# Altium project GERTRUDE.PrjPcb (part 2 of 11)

## Sheet MODULE.SchDoc: MODULE
size A3; Author: Silvio Navaretti; CompanyName: ARDUINO; DrawnBy: Silvio Navaretti; Engineer: Silvio Navaretti; Organization: ARDUINO; SheetNumber: 2; SheetTotal: 51; RevAuthor: Silvio Navaretti
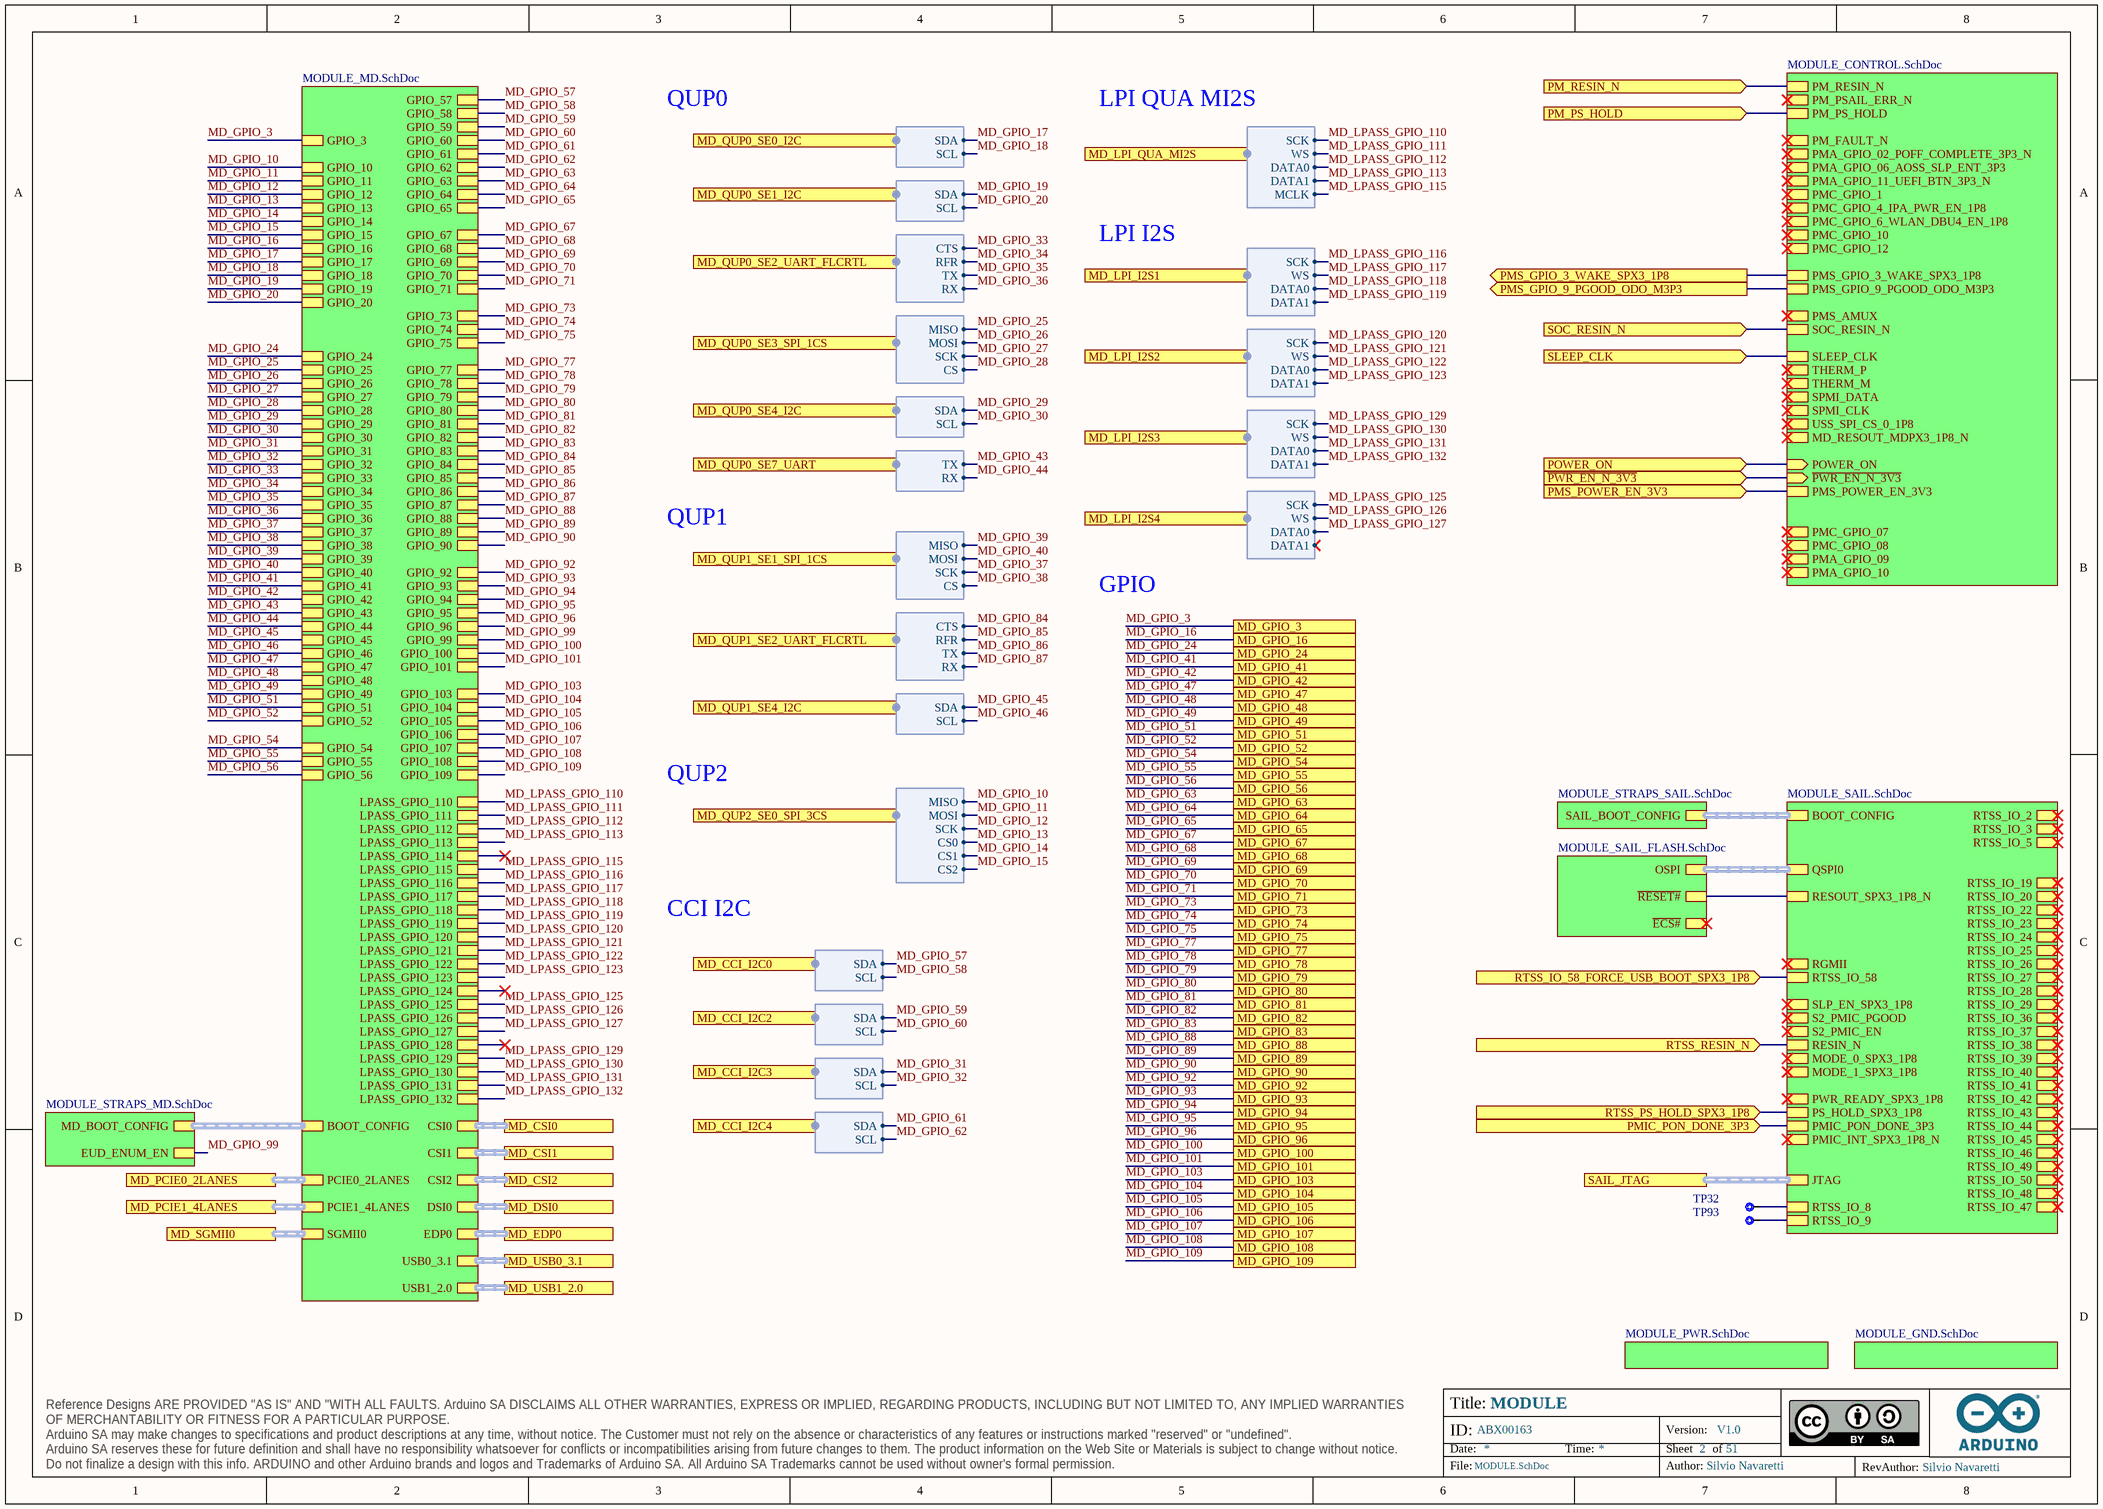
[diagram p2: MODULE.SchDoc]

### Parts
TP32  Test point 1.00mm  [TP-1.00MM]  (value not drawn)  (no BOM)
TP93  Test point 1.00mm  [TP-1.00MM]  (value not drawn)  (no BOM)

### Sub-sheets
MODULE_CONTROL = MODULE_CONTROL.SchDoc: PM_RESIN_N, PM_PSAIL_ERR_N, PM_PS_HOLD, PM_FAULT_N, PMA_GPIO_02_POFF_COMPLETE_3P3_N, PMA_GPIO_06_AOSS_SLP_ENT_3P3, PMA_GPIO_11_UEFI_BTN_3P3_N, PMC_GPIO_1, PMC_GPIO_4_IPA_PWR_EN_1P8, PMC_GPIO_6_WLAN_DBU4_EN_1P8, PMC_GPIO_10, PMC_GPIO_12, PMS_GPIO_3_WAKE_SPX3_1P8, PMS_GPIO_9_PGOOD_ODO_M3P3, PMS_AMUX, SOC_RESIN_N, SLEEP_CLK, THERM_P, THERM_M, SPMI_DATA, SPMI_CLK, USS_SPI_CS_0_1P8, MD_RESOUT_MDPX3_1P8_N, POWER_ON (in), ~{PWR_EN_N_3V3} (in), PMA_GPIO_09, PMA_GPIO_10, PMC_GPIO_07, PMC_GPIO_08, PMS_POWER_EN_3V3
MODULE_GND = MODULE_GND.SchDoc: no entries
MODULE_PWR = MODULE_PWR.SchDoc: no entries
MODULE_SAIL = MODULE_SAIL.SchDoc: JTAG (harness SOM_SAIL_JTAG), RGMII (harness SOM_SAIL_RGMII), SLP_EN_SPX3_1P8, S2_PMIC_PGOOD, S2_PMIC_EN, RESIN_N, MODE_0_SPX3_1P8, MODE_1_SPX3_1P8, PWR_READY_SPX3_1P8, PS_HOLD_SPX3_1P8, PMIC_PON_DONE_3P3, PMIC_INT_SPX3_1P8_N, BOOT_CONFIG (harness SOM_SAIL_BOOT_CONFIG), RTSS_IO_2, RTSS_IO_3, RTSS_IO_5, RTSS_IO_8, RTSS_IO_9, RTSS_IO_19, RTSS_IO_20, RTSS_IO_22, RTSS_IO_23, RTSS_IO_24, RTSS_IO_25, RTSS_IO_26, RTSS_IO_27, RTSS_IO_28, RTSS_IO_29, RTSS_IO_36, RTSS_IO_37, RTSS_IO_38, RTSS_IO_39, RTSS_IO_40, RTSS_IO_41, RTSS_IO_42, RTSS_IO_43, RTSS_IO_44, RTSS_IO_45, RTSS_IO_46, RTSS_IO_49, RTSS_IO_50, RTSS_IO_58, RTSS_IO_48, RTSS_IO_47, RESOUT_SPX3_1P8_N, QSPI0 (harness SOM_SAIL_QSPI0)
MODULE_SAIL_FLASH = MODULE_SAIL_FLASH.SchDoc: ~{RESET#}, ~{ECS#}, OSPI (harness SOM_SAIL_QSPI0)
MODULE_STRAPS_MD = MODULE_STRAPS_MD.SchDoc: MD_BOOT_CONFIG (harness SOM_MD_BOOT_CONFIG), EUD_ENUM_EN
MODULE_STRAPS_SAIL = MODULE_STRAPS_SAIL.SchDoc: SAIL_BOOT_CONFIG (harness SOM_SAIL_BOOT_CONFIG)
U_SOM_MD = MODULE_MD.SchDoc: GPIO_3, GPIO_10, GPIO_11, GPIO_12, GPIO_13, GPIO_14, GPIO_15, GPIO_16, GPIO_17, GPIO_18, GPIO_19, GPIO_20, GPIO_24, GPIO_25, GPIO_26, GPIO_27, GPIO_28, GPIO_29, GPIO_30, GPIO_31, GPIO_32, GPIO_33, GPIO_34, GPIO_35, GPIO_36, GPIO_37, GPIO_38, GPIO_39, GPIO_40, GPIO_42, GPIO_43, GPIO_45, GPIO_46, GPIO_47, GPIO_48, GPIO_52, GPIO_54, GPIO_55, GPIO_56, GPIO_57, GPIO_58, GPIO_59, GPIO_60, GPIO_61, GPIO_62, GPIO_63, GPIO_64, GPIO_65, GPIO_67, GPIO_68, GPIO_69, GPIO_70, GPIO_71, GPIO_73, GPIO_74, GPIO_75, GPIO_77, GPIO_78, GPIO_79, GPIO_80, GPIO_81, GPIO_83, GPIO_84, GPIO_85, GPIO_86, GPIO_87, GPIO_88, GPIO_89, GPIO_90, GPIO_92, GPIO_93, GPIO_94, GPIO_95, GPIO_99, GPIO_100, GPIO_101, GPIO_104, GPIO_105, GPIO_106, GPIO_107, GPIO_108, GPIO_109, LPASS_GPIO_110, LPASS_GPIO_111, LPASS_GPIO_112, LPASS_GPIO_113, LPASS_GPIO_114, LPASS_GPIO_115, LPASS_GPIO_116, LPASS_GPIO_117, LPASS_GPIO_118, LPASS_GPIO_119, LPASS_GPIO_120, LPASS_GPIO_121, LPASS_GPIO_122, LPASS_GPIO_123, LPASS_GPIO_124, LPASS_GPIO_125, LPASS_GPIO_126, LPASS_GPIO_127, LPASS_GPIO_128, LPASS_GPIO_129, LPASS_GPIO_130, LPASS_GPIO_131, LPASS_GPIO_132, SGMII0 (harness SOM_MD_SGMII0), EDP0 (harness SOM_MD_EDP0), USB0_3.1 (harness SOM_MD_USB0), USB1_2.0 (harness SOM_MD_USB1), PCIE1_4LANES (harness SOM_MD_PCIE1), BOOT_CONFIG (harness SOM_MD_BOOT_CONFIG), GPIO_44, CSI0 (harness MIPI_4LANES), CSI1 (harness MIPI_4LANES), CSI2 (harness MIPI_4LANES), DSI0 (harness MIPI_4LANES), GPIO_103, GPIO_82, GPIO_41, GPIO_96, GPIO_49, GPIO_51, PCIE0_2LANES (harness SOM_MD_PCIE0)

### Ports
MD_CCI_I2C0 (harness I2C), MD_CCI_I2C2 (harness I2C), MD_CCI_I2C3 (harness I2C), MD_CCI_I2C4 (harness I2C), MD_CSI0, MD_CSI1, MD_CSI2, MD_DSI0, MD_EDP0, MD_GPIO_3, MD_GPIO_16, MD_GPIO_24, MD_GPIO_41, MD_GPIO_42, MD_GPIO_47, MD_GPIO_48, MD_GPIO_49, MD_GPIO_51, MD_GPIO_52, MD_GPIO_54, MD_GPIO_55, MD_GPIO_56, MD_GPIO_63, MD_GPIO_64, MD_GPIO_65, MD_GPIO_67, MD_GPIO_68, MD_GPIO_69, MD_GPIO_70, MD_GPIO_71, MD_GPIO_73, MD_GPIO_74, MD_GPIO_75, MD_GPIO_77, MD_GPIO_78, MD_GPIO_79, MD_GPIO_80, MD_GPIO_81, MD_GPIO_82, MD_GPIO_83, MD_GPIO_88, MD_GPIO_89, MD_GPIO_90, MD_GPIO_92, MD_GPIO_93, MD_GPIO_94, MD_GPIO_95, MD_GPIO_96, MD_GPIO_100, MD_GPIO_101, MD_GPIO_103, MD_GPIO_104, MD_GPIO_105, MD_GPIO_106, MD_GPIO_107, MD_GPIO_108, MD_GPIO_109, MD_LPI_I2S1 (harness SOM_MD_I2S), MD_LPI_I2S2 (harness SOM_MD_I2S), MD_LPI_I2S3 (harness SOM_MD_I2S), MD_LPI_I2S4 (harness SOM_MD_I2S), MD_LPI_QUA_MI2S (harness SOM_MD_I2S_QUA), MD_PCIE0_2LANES, MD_PCIE1_4LANES, MD_QUP0_SE0_I2C (harness I2C), MD_QUP0_SE1_I2C (harness I2C), MD_QUP0_SE2_UART_FLCRTL (harness SOM_MD_UART_FLCRTL), MD_QUP0_SE3_SPI_1CS (harness SPI), MD_QUP0_SE4_I2C (harness I2C), MD_QUP0_SE7_UART (harness UART), MD_QUP1_SE1_SPI_1CS (harness SPI), MD_QUP1_SE2_UART_FLCRTL (harness SOM_MD_UART_FLCRTL), MD_QUP1_SE4_I2C (harness I2C), MD_QUP2_SE0_SPI_3CS (harness SOM_MD_SPI_3CS), MD_SGMII0, MD_USB0_3.1, MD_USB1_2.0, PM_PS_HOLD (in), PM_RESIN_N (in), PMIC_PON_DONE_3P3 (in), PMS_GPIO_3_WAKE_SPX3_1P8 (out), PMS_GPIO_9_PGOOD_ODO_M3P3 (out), PMS_POWER_EN_3V3 (in), POWER_ON (in), RTSS_IO_58_FORCE_USB_BOOT_SPX3_1P8 (in), RTSS_PS_HOLD_SPX3_1P8 (in), RTSS_RESIN_N (in), SAIL_JTAG, SLEEP_CLK (in), SOC_RESIN_N (in), ~{PWR_EN_N_3V3} (in)

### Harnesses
I2C: SDA, SCL
SOM_MD_I2S_QUA: SCK, WS, DATA0, DATA1, MCLK
SOM_MD_I2S: SCK, WS, DATA0, DATA1
SPI: SCK, MISO, MOSI, CS
SOM_MD_UART_FLCRTL: TX, CTS, RFR, RX
UART: TX, RX
SOM_MD_SPI_3CS: SCK, MISO, MOSI, CS0, CS1, CS2

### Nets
MD_GPIO_3: port MD_GPIO_3, sheet U_SOM_MD/GPIO_3
MD_GPIO_10: sheet U_SOM_MD/GPIO_10, port MD_QUP2_SE0_SPI_3CS.MISO
MD_GPIO_11: sheet U_SOM_MD/GPIO_11, port MD_QUP2_SE0_SPI_3CS.MOSI
MD_GPIO_12: sheet U_SOM_MD/GPIO_12, port MD_QUP2_SE0_SPI_3CS.SCK
MD_GPIO_13: sheet U_SOM_MD/GPIO_13, port MD_QUP2_SE0_SPI_3CS.CS0
MD_GPIO_14: sheet U_SOM_MD/GPIO_14, port MD_QUP2_SE0_SPI_3CS.CS1
MD_GPIO_15: sheet U_SOM_MD/GPIO_15, port MD_QUP2_SE0_SPI_3CS.CS2
MD_GPIO_16: port MD_GPIO_16, sheet U_SOM_MD/GPIO_16
MD_GPIO_17: sheet U_SOM_MD/GPIO_17, port MD_QUP0_SE0_I2C.SDA
MD_GPIO_18: sheet U_SOM_MD/GPIO_18, port MD_QUP0_SE0_I2C.SCL
MD_GPIO_19: sheet U_SOM_MD/GPIO_19, port MD_QUP0_SE1_I2C.SDA
MD_GPIO_20: sheet U_SOM_MD/GPIO_20, port MD_QUP0_SE1_I2C.SCL
MD_GPIO_24: port MD_GPIO_24, sheet U_SOM_MD/GPIO_24
MD_GPIO_25: sheet U_SOM_MD/GPIO_25, port MD_QUP0_SE3_SPI_1CS.MISO
MD_GPIO_26: sheet U_SOM_MD/GPIO_26, port MD_QUP0_SE3_SPI_1CS.MOSI
MD_GPIO_27: sheet U_SOM_MD/GPIO_27, port MD_QUP0_SE3_SPI_1CS.SCK
MD_GPIO_28: sheet U_SOM_MD/GPIO_28, port MD_QUP0_SE3_SPI_1CS.CS
MD_GPIO_29: sheet U_SOM_MD/GPIO_29, port MD_QUP0_SE4_I2C.SDA
MD_GPIO_30: sheet U_SOM_MD/GPIO_30, port MD_QUP0_SE4_I2C.SCL
MD_GPIO_31: sheet U_SOM_MD/GPIO_31, port MD_CCI_I2C3.SDA  [project net MD_CCI_I2C3.SDA]
MD_GPIO_32: sheet U_SOM_MD/GPIO_32, port MD_CCI_I2C3.SCL  [project net MD_CCI_I2C3.SCL]
MD_GPIO_33: sheet U_SOM_MD/GPIO_33, port MD_QUP0_SE2_UART_FLCRTL.CTS
MD_GPIO_34: sheet U_SOM_MD/GPIO_34, port MD_QUP0_SE2_UART_FLCRTL.RFR
MD_GPIO_35: sheet U_SOM_MD/GPIO_35, port MD_QUP0_SE2_UART_FLCRTL.TX
MD_GPIO_36: sheet U_SOM_MD/GPIO_36, port MD_QUP0_SE2_UART_FLCRTL.RX
MD_GPIO_37: sheet U_SOM_MD/GPIO_37, port MD_QUP1_SE1_SPI_1CS.SCK
MD_GPIO_38: sheet U_SOM_MD/GPIO_38, port MD_QUP1_SE1_SPI_1CS.CS
MD_GPIO_39: sheet U_SOM_MD/GPIO_39, port MD_QUP1_SE1_SPI_1CS.MISO
MD_GPIO_40: sheet U_SOM_MD/GPIO_40, port MD_QUP1_SE1_SPI_1CS.MOSI
MD_GPIO_41: port MD_GPIO_41, sheet U_SOM_MD/GPIO_41
MD_GPIO_42: port MD_GPIO_42, sheet U_SOM_MD/GPIO_42
MD_GPIO_43: sheet U_SOM_MD/GPIO_43, port MD_QUP0_SE7_UART.TX
MD_GPIO_44: sheet U_SOM_MD/GPIO_44, port MD_QUP0_SE7_UART.RX
MD_GPIO_45: sheet U_SOM_MD/GPIO_45, port MD_QUP1_SE4_I2C.SDA
MD_GPIO_46: sheet U_SOM_MD/GPIO_46, port MD_QUP1_SE4_I2C.SCL
MD_GPIO_47: port MD_GPIO_47, sheet U_SOM_MD/GPIO_47
MD_GPIO_48: port MD_GPIO_48, sheet U_SOM_MD/GPIO_48
MD_GPIO_49: port MD_GPIO_49, sheet U_SOM_MD/GPIO_49
MD_GPIO_51: port MD_GPIO_51, sheet U_SOM_MD/GPIO_51
MD_GPIO_52: port MD_GPIO_52, sheet U_SOM_MD/GPIO_52
MD_GPIO_54: port MD_GPIO_54, sheet U_SOM_MD/GPIO_54
MD_GPIO_55: port MD_GPIO_55, sheet U_SOM_MD/GPIO_55
MD_GPIO_56: port MD_GPIO_56, sheet U_SOM_MD/GPIO_56
MD_GPIO_57: sheet U_SOM_MD/GPIO_57, port MD_CCI_I2C0.SDA  [project net MD_CCI_I2C0.SDA]
MD_GPIO_58: sheet U_SOM_MD/GPIO_58, port MD_CCI_I2C0.SCL  [project net MD_CCI_I2C0.SCL]
MD_GPIO_59: sheet U_SOM_MD/GPIO_59, port MD_CCI_I2C2.SDA  [project net MD_CCI_I2C2.SDA]
MD_GPIO_60: sheet U_SOM_MD/GPIO_60, port MD_CCI_I2C2.SCL  [project net MD_CCI_I2C2.SCL]
MD_GPIO_61: sheet U_SOM_MD/GPIO_61, port MD_CCI_I2C4.SDA  [project net MD_CCI_I2C4.SDA]
MD_GPIO_62: sheet U_SOM_MD/GPIO_62, port MD_CCI_I2C4.SCL  [project net MD_CCI_I2C4.SCL]
MD_GPIO_63: port MD_GPIO_63, sheet U_SOM_MD/GPIO_63
MD_GPIO_64: port MD_GPIO_64, sheet U_SOM_MD/GPIO_64
MD_GPIO_65: port MD_GPIO_65, sheet U_SOM_MD/GPIO_65
MD_GPIO_67: port MD_GPIO_67, sheet U_SOM_MD/GPIO_67
MD_GPIO_68: port MD_GPIO_68, sheet U_SOM_MD/GPIO_68
MD_GPIO_69: port MD_GPIO_69, sheet U_SOM_MD/GPIO_69
MD_GPIO_70: port MD_GPIO_70, sheet U_SOM_MD/GPIO_70
MD_GPIO_71: port MD_GPIO_71, sheet U_SOM_MD/GPIO_71
MD_GPIO_73: port MD_GPIO_73, sheet U_SOM_MD/GPIO_73
MD_GPIO_74: port MD_GPIO_74, sheet U_SOM_MD/GPIO_74
MD_GPIO_75: port MD_GPIO_75, sheet U_SOM_MD/GPIO_75
MD_GPIO_77: port MD_GPIO_77, sheet U_SOM_MD/GPIO_77
MD_GPIO_78: port MD_GPIO_78, sheet U_SOM_MD/GPIO_78
MD_GPIO_79: port MD_GPIO_79, sheet U_SOM_MD/GPIO_79
MD_GPIO_80: port MD_GPIO_80, sheet U_SOM_MD/GPIO_80
MD_GPIO_81: port MD_GPIO_81, sheet U_SOM_MD/GPIO_81
MD_GPIO_82: port MD_GPIO_82, sheet U_SOM_MD/GPIO_82
MD_GPIO_83: port MD_GPIO_83, sheet U_SOM_MD/GPIO_83
MD_GPIO_84: sheet U_SOM_MD/GPIO_84, port MD_QUP1_SE2_UART_FLCRTL.CTS  [project net CTS_1V8]
MD_GPIO_85: sheet U_SOM_MD/GPIO_85, port MD_QUP1_SE2_UART_FLCRTL.RFR
MD_GPIO_86: sheet U_SOM_MD/GPIO_86, port MD_QUP1_SE2_UART_FLCRTL.TX
MD_GPIO_87: sheet U_SOM_MD/GPIO_87, port MD_QUP1_SE2_UART_FLCRTL.RX
MD_GPIO_88: port MD_GPIO_88, sheet U_SOM_MD/GPIO_88
MD_GPIO_89: port MD_GPIO_89, sheet U_SOM_MD/GPIO_89
MD_GPIO_90: port MD_GPIO_90, sheet U_SOM_MD/GPIO_90
MD_GPIO_92: port MD_GPIO_92, sheet U_SOM_MD/GPIO_92
MD_GPIO_93: port MD_GPIO_93, sheet U_SOM_MD/GPIO_93
MD_GPIO_94: port MD_GPIO_94, sheet U_SOM_MD/GPIO_94
MD_GPIO_95: port MD_GPIO_95, sheet U_SOM_MD/GPIO_95
MD_GPIO_96: port MD_GPIO_96, sheet U_SOM_MD/GPIO_96
MD_GPIO_99: sheet U_SOM_MD/GPIO_99, sheet MODULE_STRAPS_MD/EUD_ENUM_EN
MD_GPIO_100: port MD_GPIO_100, sheet U_SOM_MD/GPIO_100
MD_GPIO_101: port MD_GPIO_101, sheet U_SOM_MD/GPIO_101
MD_GPIO_103: port MD_GPIO_103, sheet U_SOM_MD/GPIO_103
MD_GPIO_104: port MD_GPIO_104, sheet U_SOM_MD/GPIO_104
MD_GPIO_105: port MD_GPIO_105, sheet U_SOM_MD/GPIO_105
MD_GPIO_106: port MD_GPIO_106, sheet U_SOM_MD/GPIO_106
MD_GPIO_107: port MD_GPIO_107, sheet U_SOM_MD/GPIO_107
MD_GPIO_108: port MD_GPIO_108, sheet U_SOM_MD/GPIO_108
MD_GPIO_109: port MD_GPIO_109, sheet U_SOM_MD/GPIO_109
MD_LPASS_GPIO_110: sheet U_SOM_MD/LPASS_GPIO_110, port MD_LPI_QUA_MI2S.SCK
MD_LPASS_GPIO_111: sheet U_SOM_MD/LPASS_GPIO_111, port MD_LPI_QUA_MI2S.WS
MD_LPASS_GPIO_112: sheet U_SOM_MD/LPASS_GPIO_112, port MD_LPI_QUA_MI2S.DATA0
MD_LPASS_GPIO_113: sheet U_SOM_MD/LPASS_GPIO_113, port MD_LPI_QUA_MI2S.DATA1
MD_LPASS_GPIO_115: sheet U_SOM_MD/LPASS_GPIO_115, port MD_LPI_QUA_MI2S.MCLK
MD_LPASS_GPIO_116: sheet U_SOM_MD/LPASS_GPIO_116, port MD_LPI_I2S1.SCK  [project net I2S_SCK]
MD_LPASS_GPIO_117: sheet U_SOM_MD/LPASS_GPIO_117, port MD_LPI_I2S1.WS  [project net I2S_WS]
MD_LPASS_GPIO_118: sheet U_SOM_MD/LPASS_GPIO_118, port MD_LPI_I2S1.DATA0  [project net I2S_DATA0]
MD_LPASS_GPIO_119: sheet U_SOM_MD/LPASS_GPIO_119, port MD_LPI_I2S1.DATA1  [project net I2S_DATA1]
MD_LPASS_GPIO_120: sheet U_SOM_MD/LPASS_GPIO_120, port MD_LPI_I2S2.SCK
MD_LPASS_GPIO_121: sheet U_SOM_MD/LPASS_GPIO_121, port MD_LPI_I2S2.WS
MD_LPASS_GPIO_122: sheet U_SOM_MD/LPASS_GPIO_122, port MD_LPI_I2S2.DATA0
MD_LPASS_GPIO_123: sheet U_SOM_MD/LPASS_GPIO_123, port MD_LPI_I2S2.DATA1
MD_LPASS_GPIO_125: sheet U_SOM_MD/LPASS_GPIO_125, port MD_LPI_I2S4.SCK
MD_LPASS_GPIO_126: sheet U_SOM_MD/LPASS_GPIO_126, port MD_LPI_I2S4.WS
MD_LPASS_GPIO_127: sheet U_SOM_MD/LPASS_GPIO_127, port MD_LPI_I2S4.DATA0
MD_LPASS_GPIO_129: sheet U_SOM_MD/LPASS_GPIO_129, port MD_LPI_I2S3.SCK
MD_LPASS_GPIO_130: sheet U_SOM_MD/LPASS_GPIO_130, port MD_LPI_I2S3.WS
MD_LPASS_GPIO_131: sheet U_SOM_MD/LPASS_GPIO_131, port MD_LPI_I2S3.DATA0
MD_LPASS_GPIO_132: sheet U_SOM_MD/LPASS_GPIO_132, port MD_LPI_I2S3.DATA1
PM_PS_HOLD: port PM_PS_HOLD, sheet MODULE_CONTROL/PM_PS_HOLD
RTSS_IO_58_FORCE_USB_BOOT_SPX3_1P8: port RTSS_IO_58_FORCE_USB_BOOT_SPX3_1P8, sheet MODULE_SAIL/RTSS_IO_58
RTSS_RESIN_N: port RTSS_RESIN_N, sheet MODULE_SAIL/RESIN_N
SLEEP_CLK: port SLEEP_CLK, sheet MODULE_CONTROL/SLEEP_CLK
NetMODULE1_A6: port PM_RESIN_N, sheet MODULE_CONTROL/PM_RESIN_N
NetMODULE1_AY42: port PMS_GPIO_9_PGOOD_ODO_M3P3, sheet MODULE_CONTROL/PMS_GPIO_9_PGOOD_ODO_M3P3
NetMODULE1_AY45: port PMIC_PON_DONE_3P3, sheet MODULE_SAIL/PMIC_PON_DONE_3P3
NetMODULE1_BA43: port PMS_POWER_EN_3V3, sheet MODULE_CONTROL/PMS_POWER_EN_3V3
NetMODULE1_BB43: port RTSS_PS_HOLD_SPX3_1P8, sheet MODULE_SAIL/PS_HOLD_SPX3_1P8
NetMODULE1_BB44: port PMS_GPIO_3_WAKE_SPX3_1P8, sheet MODULE_CONTROL/PMS_GPIO_3_WAKE_SPX3_1P8
NetMODULE1_BD41: sheet MODULE_SAIL/RESOUT_SPX3_1P8_N, sheet MODULE_SAIL_FLASH/~{RESET#}
NetMODULE1_BE36: TP93.X ; sheet MODULE_SAIL/RTSS_IO_9
NetMODULE1_BF36: TP32.X ; sheet MODULE_SAIL/RTSS_IO_8
NetMODULE1_D28: port SOC_RESIN_N, sheet MODULE_CONTROL/SOC_RESIN_N
NetR349_2: port POWER_ON, sheet MODULE_CONTROL/POWER_ON
NetR350_2: port ~{PWR_EN_N_3V3}, sheet MODULE_CONTROL/~{PWR_EN_N_3V3}

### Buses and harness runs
harness port MD_CSI0 = sheet U_SOM_MD/CSI0
harness port MD_CSI1 = sheet U_SOM_MD/CSI1
harness port MD_CSI2 = sheet U_SOM_MD/CSI2
harness port MD_DSI0 = sheet U_SOM_MD/DSI0
harness port MD_EDP0 = sheet U_SOM_MD/EDP0
harness port MD_PCIE0_2LANES = sheet U_SOM_MD/PCIE0_2LANES
harness port MD_PCIE1_4LANES = sheet U_SOM_MD/PCIE1_4LANES
harness port MD_SGMII0 = sheet U_SOM_MD/SGMII0
harness port MD_USB0_3.1 = sheet U_SOM_MD/USB0_3.1
harness port MD_USB1_2.0 = sheet U_SOM_MD/USB1_2.0
harness port SAIL_JTAG = sheet MODULE_SAIL/JTAG
harness sheet MODULE_SAIL/BOOT_CONFIG = sheet MODULE_STRAPS_SAIL/SAIL_BOOT_CONFIG
harness sheet MODULE_SAIL/QSPI0 = sheet MODULE_SAIL_FLASH/OSPI
harness sheet MODULE_STRAPS_MD/MD_BOOT_CONFIG = sheet U_SOM_MD/BOOT_CONFIG

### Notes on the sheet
- QUP0
- LPI QUA MI2S
- LPI I2S
- QUP1
- GPIO
- QUP2
- CCI I2C

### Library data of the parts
TP32 TP93 = UT0013-A.6: Part Number: This is not a component

## Sheet MODULE_GND.SchDoc: MODULE GND
size A3; Author: Silvio Navaretti; CompanyName: ARDUINO; DrawnBy: Silvio Navaretti; Engineer: Silvio Navaretti; Organization: ARDUINO; SheetNumber: 10; SheetTotal: 51; RevAuthor: Silvio Navaretti
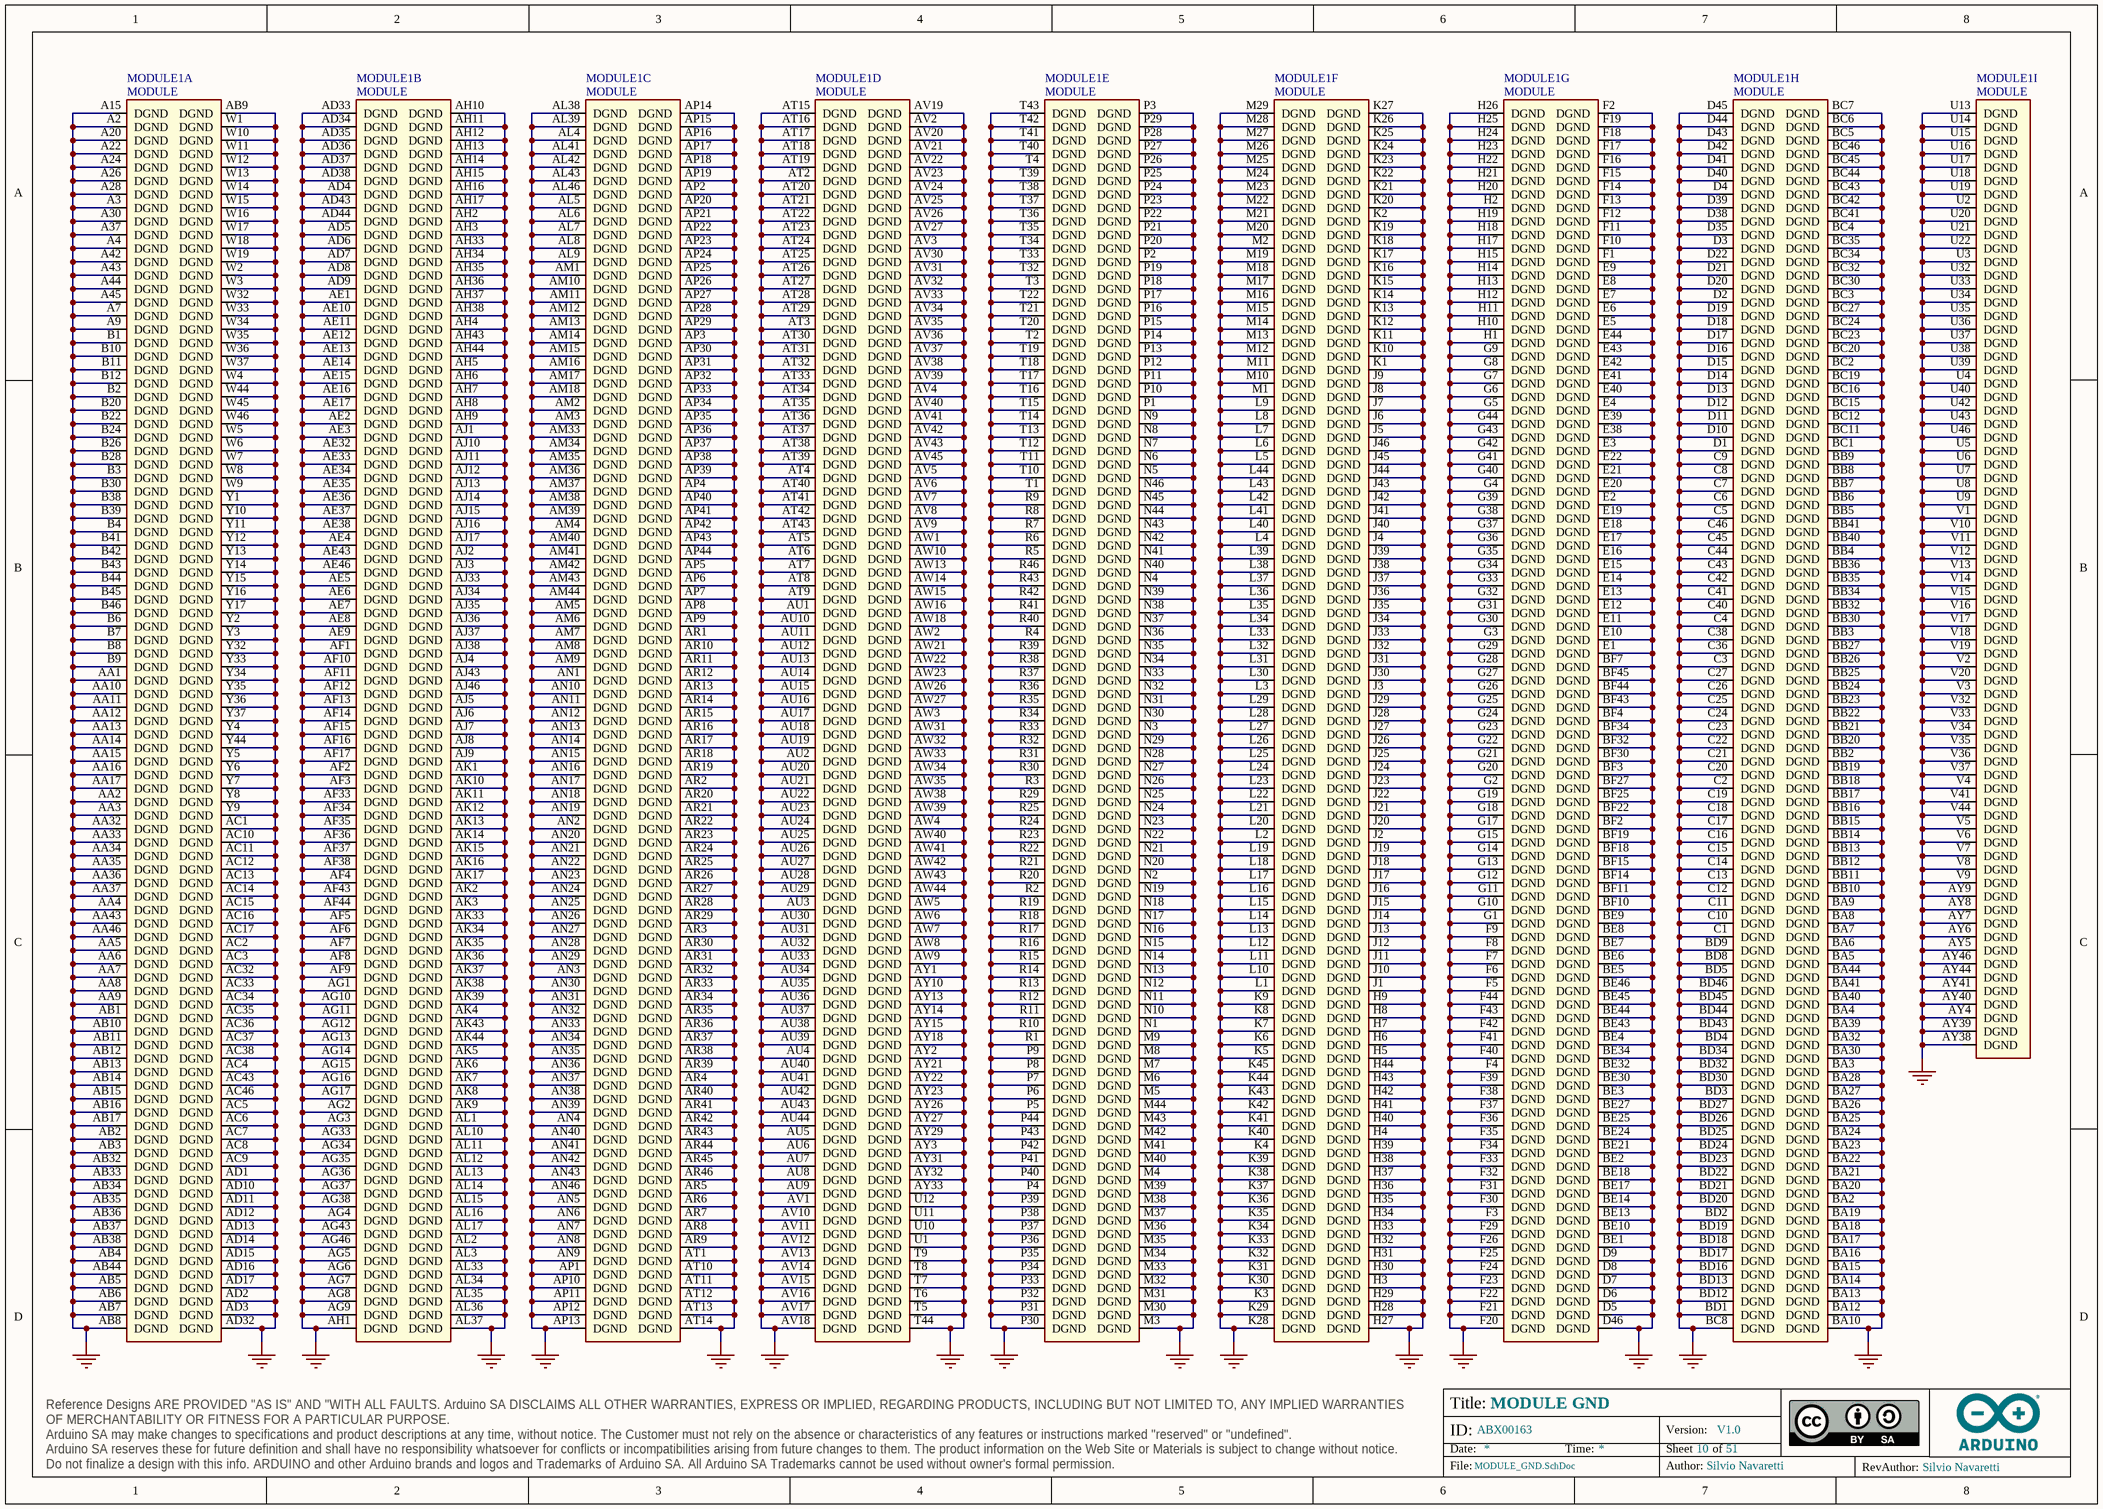
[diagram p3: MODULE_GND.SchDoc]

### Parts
MODULE1  MODULE  [MODULE]  (parts A,B,C,D,E,F,G,H,I of 22)

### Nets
GND: MODULE1.A2(DGND) MODULE1.A3(DGND) MODULE1.A4(DGND) MODULE1.A7(DGND) MODULE1.A9(DGND) MODULE1.A15(DGND) MODULE1.A20(DGND) MODULE1.A22(DGND) MODULE1.A24(DGND) MODULE1.A26(DGND) MODULE1.A28(DGND) MODULE1.A30(DGND) MODULE1.A37(DGND) MODULE1.A42(DGND) MODULE1.A43(DGND) MODULE1.A44(DGND) MODULE1.A45(DGND) MODULE1.AA1(DGND) MODULE1.AA2(DGND) MODULE1.AA3(DGND) MODULE1.AA4(DGND) MODULE1.AA5(DGND) MODULE1.AA6(DGND) MODULE1.AA7(DGND) MODULE1.AA8(DGND) MODULE1.AA9(DGND) MODULE1.AA10(DGND) MODULE1.AA11(DGND) MODULE1.AA12(DGND) MODULE1.AA13(DGND) MODULE1.AA14(DGND) MODULE1.AA15(DGND) MODULE1.AA16(DGND) MODULE1.AA17(DGND) MODULE1.AA32(DGND) MODULE1.AA33(DGND) MODULE1.AA34(DGND) MODULE1.AA35(DGND) MODULE1.AA36(DGND) MODULE1.AA37(DGND) MODULE1.AA43(DGND) MODULE1.AA46(DGND) MODULE1.AB1(DGND) MODULE1.AB2(DGND) MODULE1.AB3(DGND) MODULE1.AB4(DGND) MODULE1.AB5(DGND) MODULE1.AB6(DGND) MODULE1.AB7(DGND) MODULE1.AB8(DGND) MODULE1.AB9(DGND) MODULE1.AB10(DGND) MODULE1.AB11(DGND) MODULE1.AB12(DGND) MODULE1.AB13(DGND) MODULE1.AB14(DGND) MODULE1.AB15(DGND) MODULE1.AB16(DGND) MODULE1.AB17(DGND) MODULE1.AB32(DGND) MODULE1.AB33(DGND) MODULE1.AB34(DGND) MODULE1.AB35(DGND) MODULE1.AB36(DGND) MODULE1.AB37(DGND) MODULE1.AB38(DGND) MODULE1.AB44(DGND) MODULE1.AC1(DGND) MODULE1.AC2(DGND) MODULE1.AC3(DGND) MODULE1.AC4(DGND) MODULE1.AC5(DGND) MODULE1.AC6(DGND) MODULE1.AC7(DGND) MODULE1.AC8(DGND) MODULE1.AC9(DGND) MODULE1.AC10(DGND) MODULE1.AC11(DGND) MODULE1.AC12(DGND) MODULE1.AC13(DGND) MODULE1.AC14(DGND) MODULE1.AC15(DGND) MODULE1.AC16(DGND) MODULE1.AC17(DGND) MODULE1.AC32(DGND) MODULE1.AC33(DGND) MODULE1.AC34(DGND) MODULE1.AC35(DGND) MODULE1.AC36(DGND) MODULE1.AC37(DGND) MODULE1.AC38(DGND) MODULE1.AC43(DGND) MODULE1.AC46(DGND) MODULE1.AD1(DGND) MODULE1.AD2(DGND) MODULE1.AD3(DGND) MODULE1.AD4(DGND) MODULE1.AD5(DGND) MODULE1.AD6(DGND) MODULE1.AD7(DGND) MODULE1.AD8(DGND) MODULE1.AD9(DGND) MODULE1.AD10(DGND) MODULE1.AD11(DGND) MODULE1.AD12(DGND) MODULE1.AD13(DGND) MODULE1.AD14(DGND) MODULE1.AD15(DGND) MODULE1.AD16(DGND) MODULE1.AD17(DGND) MODULE1.AD32(DGND) MODULE1.AD33(DGND) MODULE1.AD34(DGND) MODULE1.AD35(DGND) MODULE1.AD36(DGND) MODULE1.AD37(DGND) MODULE1.AD38(DGND) MODULE1.AD43(DGND) MODULE1.AD44(DGND) MODULE1.AE1(DGND) MODULE1.AE2(DGND) MODULE1.AE3(DGND) MODULE1.AE4(DGND) MODULE1.AE5(DGND) MODULE1.AE6(DGND) MODULE1.AE7(DGND) MODULE1.AE8(DGND) MODULE1.AE9(DGND) MODULE1.AE10(DGND) MODULE1.AE11(DGND) MODULE1.AE12(DGND) MODULE1.AE13(DGND) MODULE1.AE14(DGND) MODULE1.AE15(DGND) MODULE1.AE16(DGND) MODULE1.AE17(DGND) MODULE1.AE32(DGND) MODULE1.AE33(DGND) MODULE1.AE34(DGND) MODULE1.AE35(DGND) MODULE1.AE36(DGND) MODULE1.AE37(DGND) MODULE1.AE38(DGND) MODULE1.AE43(DGND) MODULE1.AE46(DGND) MODULE1.AF1(DGND) MODULE1.AF2(DGND) MODULE1.AF3(DGND) MODULE1.AF4(DGND) MODULE1.AF5(DGND) MODULE1.AF6(DGND) MODULE1.AF7(DGND) MODULE1.AF8(DGND) MODULE1.AF9(DGND) MODULE1.AF10(DGND) MODULE1.AF11(DGND) MODULE1.AF12(DGND) MODULE1.AF13(DGND) MODULE1.AF14(DGND) MODULE1.AF15(DGND) MODULE1.AF16(DGND) MODULE1.AF17(DGND) MODULE1.AF33(DGND) MODULE1.AF34(DGND) MODULE1.AF35(DGND) MODULE1.AF36(DGND) MODULE1.AF37(DGND) MODULE1.AF38(DGND) MODULE1.AF43(DGND) MODULE1.AF44(DGND) MODULE1.AG1(DGND) MODULE1.AG2(DGND) MODULE1.AG3(DGND) MODULE1.AG4(DGND) MODULE1.AG5(DGND) MODULE1.AG6(DGND) MODULE1.AG7(DGND) MODULE1.AG8(DGND) MODULE1.AG9(DGND) MODULE1.AG10(DGND) MODULE1.AG11(DGND) MODULE1.AG12(DGND) MODULE1.AG13(DGND) MODULE1.AG14(DGND) MODULE1.AG15(DGND) MODULE1.AG16(DGND) MODULE1.AG17(DGND) MODULE1.AG33(DGND) MODULE1.AG34(DGND) MODULE1.AG35(DGND) MODULE1.AG36(DGND) MODULE1.AG37(DGND) MODULE1.AG38(DGND) MODULE1.AG43(DGND) MODULE1.AG46(DGND) MODULE1.AH1(DGND) MODULE1.AH2(DGND) MODULE1.AH3(DGND) MODULE1.AH4(DGND) MODULE1.AH5(DGND) MODULE1.AH6(DGND) MODULE1.AH7(DGND) MODULE1.AH8(DGND) MODULE1.AH9(DGND) MODULE1.AH10(DGND) MODULE1.AH11(DGND) MODULE1.AH12(DGND) MODULE1.AH13(DGND) MODULE1.AH14(DGND) MODULE1.AH15(DGND) MODULE1.AH16(DGND) MODULE1.AH17(DGND) MODULE1.AH33(DGND) MODULE1.AH34(DGND) MODULE1.AH35(DGND) MODULE1.AH36(DGND) MODULE1.AH37(DGND) MODULE1.AH38(DGND) MODULE1.AH43(DGND) MODULE1.AH44(DGND) MODULE1.AJ1(DGND) MODULE1.AJ2(DGND) MODULE1.AJ3(DGND) MODULE1.AJ4(DGND) MODULE1.AJ5(DGND) MODULE1.AJ6(DGND) MODULE1.AJ7(DGND) MODULE1.AJ8(DGND) MODULE1.AJ9(DGND) MODULE1.AJ10(DGND) MODULE1.AJ11(DGND) MODULE1.AJ12(DGND) MODULE1.AJ13(DGND) MODULE1.AJ14(DGND) MODULE1.AJ15(DGND) MODULE1.AJ16(DGND) MODULE1.AJ17(DGND) MODULE1.AJ33(DGND) MODULE1.AJ34(DGND) MODULE1.AJ35(DGND) MODULE1.AJ36(DGND) MODULE1.AJ37(DGND) MODULE1.AJ38(DGND) MODULE1.AJ43(DGND) MODULE1.AJ46(DGND) MODULE1.AK1(DGND) MODULE1.AK2(DGND) MODULE1.AK3(DGND) MODULE1.AK4(DGND) MODULE1.AK5(DGND) MODULE1.AK6(DGND) MODULE1.AK7(DGND) MODULE1.AK8(DGND) MODULE1.AK9(DGND) MODULE1.AK10(DGND) MODULE1.AK11(DGND) MODULE1.AK12(DGND) MODULE1.AK13(DGND) MODULE1.AK14(DGND) MODULE1.AK15(DGND) MODULE1.AK16(DGND) MODULE1.AK17(DGND) MODULE1.AK33(DGND) MODULE1.AK34(DGND) MODULE1.AK35(DGND) MODULE1.AK36(DGND) MODULE1.AK37(DGND) MODULE1.AK38(DGND) MODULE1.AK39(DGND) MODULE1.AK43(DGND) MODULE1.AK44(DGND) MODULE1.AL1(DGND) MODULE1.AL2(DGND) MODULE1.AL3(DGND) MODULE1.AL4(DGND) MODULE1.AL5(DGND) MODULE1.AL6(DGND) MODULE1.AL7(DGND) MODULE1.AL8(DGND) MODULE1.AL9(DGND) MODULE1.AL10(DGND) MODULE1.AL11(DGND) MODULE1.AL12(DGND) MODULE1.AL13(DGND) MODULE1.AL14(DGND) MODULE1.AL15(DGND) MODULE1.AL16(DGND) MODULE1.AL17(DGND) MODULE1.AL33(DGND) MODULE1.AL34(DGND) MODULE1.AL35(DGND) MODULE1.AL36(DGND) MODULE1.AL37(DGND) MODULE1.AL38(DGND) MODULE1.AL39(DGND) MODULE1.AL41(DGND) MODULE1.AL42(DGND) MODULE1.AL43(DGND) MODULE1.AL46(DGND) MODULE1.AM1(DGND) MODULE1.AM2(DGND) MODULE1.AM3(DGND) MODULE1.AM4(DGND) MODULE1.AM5(DGND) MODULE1.AM6(DGND) MODULE1.AM7(DGND) MODULE1.AM8(DGND) MODULE1.AM9(DGND) MODULE1.AM10(DGND) MODULE1.AM11(DGND) MODULE1.AM12(DGND) MODULE1.AM13(DGND) MODULE1.AM14(DGND) MODULE1.AM15(DGND) MODULE1.AM16(DGND) MODULE1.AM17(DGND) MODULE1.AM18(DGND) MODULE1.AM33(DGND) MODULE1.AM34(DGND) MODULE1.AM35(DGND) MODULE1.AM36(DGND) MODULE1.AM37(DGND) MODULE1.AM38(DGND) MODULE1.AM39(DGND) MODULE1.AM40(DGND) MODULE1.AM41(DGND) MODULE1.AM42(DGND) MODULE1.AM43(DGND) MODULE1.AM44(DGND) MODULE1.AN1(DGND) MODULE1.AN2(DGND) MODULE1.AN3(DGND) MODULE1.AN4(DGND) MODULE1.AN5(DGND) MODULE1.AN6(DGND) MODULE1.AN7(DGND) MODULE1.AN8(DGND) MODULE1.AN9(DGND) MODULE1.AN10(DGND) MODULE1.AN11(DGND) MODULE1.AN12(DGND) MODULE1.AN13(DGND) MODULE1.AN14(DGND) MODULE1.AN15(DGND) MODULE1.AN16(DGND) MODULE1.AN17(DGND) MODULE1.AN18(DGND) MODULE1.AN19(DGND) MODULE1.AN20(DGND) MODULE1.AN21(DGND) MODULE1.AN22(DGND) MODULE1.AN23(DGND) MODULE1.AN24(DGND) MODULE1.AN25(DGND) MODULE1.AN26(DGND) MODULE1.AN27(DGND) MODULE1.AN28(DGND) MODULE1.AN29(DGND) MODULE1.AN30(DGND) MODULE1.AN31(DGND) MODULE1.AN32(DGND) MODULE1.AN33(DGND) MODULE1.AN34(DGND) MODULE1.AN35(DGND) MODULE1.AN36(DGND) MODULE1.AN37(DGND) MODULE1.AN38(DGND) MODULE1.AN39(DGND) MODULE1.AN40(DGND) MODULE1.AN41(DGND) MODULE1.AN42(DGND) MODULE1.AN43(DGND) MODULE1.AN46(DGND) MODULE1.AP1(DGND) MODULE1.AP2(DGND) MODULE1.AP3(DGND) MODULE1.AP4(DGND) MODULE1.AP5(DGND) MODULE1.AP6(DGND) MODULE1.AP7(DGND) MODULE1.AP8(DGND) MODULE1.AP9(DGND) MODULE1.AP10(DGND) MODULE1.AP11(DGND) MODULE1.AP12(DGND) MODULE1.AP13(DGND) MODULE1.AP14(DGND) MODULE1.AP15(DGND) MODULE1.AP16(DGND) MODULE1.AP17(DGND) MODULE1.AP18(DGND) MODULE1.AP19(DGND) MODULE1.AP20(DGND) MODULE1.AP21(DGND) MODULE1.AP22(DGND) MODULE1.AP23(DGND) MODULE1.AP24(DGND) MODULE1.AP25(DGND) MODULE1.AP26(DGND) MODULE1.AP27(DGND) MODULE1.AP28(DGND) MODULE1.AP29(DGND) MODULE1.AP30(DGND) MODULE1.AP31(DGND) MODULE1.AP32(DGND) MODULE1.AP33(DGND) MODULE1.AP34(DGND) MODULE1.AP35(DGND) MODULE1.AP36(DGND) MODULE1.AP37(DGND) MODULE1.AP38(DGND) MODULE1.AP39(DGND) MODULE1.AP40(DGND) MODULE1.AP41(DGND) MODULE1.AP42(DGND) MODULE1.AP43(DGND) MODULE1.AP44(DGND) MODULE1.AR1(DGND) MODULE1.AR2(DGND) MODULE1.AR3(DGND) MODULE1.AR4(DGND) MODULE1.AR5(DGND) MODULE1.AR6(DGND) MODULE1.AR7(DGND) MODULE1.AR8(DGND) MODULE1.AR9(DGND) MODULE1.AR10(DGND) MODULE1.AR11(DGND) MODULE1.AR12(DGND) MODULE1.AR13(DGND) MODULE1.AR14(DGND) MODULE1.AR15(DGND) MODULE1.AR16(DGND) MODULE1.AR17(DGND) MODULE1.AR18(DGND) MODULE1.AR19(DGND) MODULE1.AR20(DGND) MODULE1.AR21(DGND) MODULE1.AR22(DGND) MODULE1.AR23(DGND) MODULE1.AR24(DGND) MODULE1.AR25(DGND) MODULE1.AR26(DGND) MODULE1.AR27(DGND) MODULE1.AR28(DGND) MODULE1.AR29(DGND) MODULE1.AR30(DGND) MODULE1.AR31(DGND) MODULE1.AR32(DGND) MODULE1.AR33(DGND) MODULE1.AR34(DGND) MODULE1.AR35(DGND) MODULE1.AR36(DGND) MODULE1.AR37(DGND) MODULE1.AR38(DGND) MODULE1.AR39(DGND) MODULE1.AR40(DGND) MODULE1.AR41(DGND) MODULE1.AR42(DGND) MODULE1.AR43(DGND) MODULE1.AR44(DGND) MODULE1.AR45(DGND) MODULE1.AR46(DGND) MODULE1.AT1(DGND) MODULE1.AT2(DGND) MODULE1.AT3(DGND) MODULE1.AT4(DGND) MODULE1.AT5(DGND) MODULE1.AT6(DGND) MODULE1.AT7(DGND) MODULE1.AT8(DGND) MODULE1.AT9(DGND) MODULE1.AT10(DGND) MODULE1.AT11(DGND) MODULE1.AT12(DGND) MODULE1.AT13(DGND) MODULE1.AT14(DGND) MODULE1.AT15(DGND) MODULE1.AT16(DGND) MODULE1.AT17(DGND) MODULE1.AT18(DGND) MODULE1.AT19(DGND) MODULE1.AT20(DGND) MODULE1.AT21(DGND) MODULE1.AT22(DGND) MODULE1.AT23(DGND) MODULE1.AT24(DGND) MODULE1.AT25(DGND) MODULE1.AT26(DGND) MODULE1.AT27(DGND) MODULE1.AT28(DGND) MODULE1.AT29(DGND) MODULE1.AT30(DGND) MODULE1.AT31(DGND) MODULE1.AT32(DGND) MODULE1.AT33(DGND) MODULE1.AT34(DGND) MODULE1.AT35(DGND) MODULE1.AT36(DGND) MODULE1.AT37(DGND) MODULE1.AT38(DGND) MODULE1.AT39(DGND) MODULE1.AT40(DGND) MODULE1.AT41(DGND) MODULE1.AT42(DGND) MODULE1.AT43(DGND) MODULE1.AU1(DGND) MODULE1.AU2(DGND) MODULE1.AU3(DGND) MODULE1.AU4(DGND) MODULE1.AU5(DGND) MODULE1.AU6(DGND) MODULE1.AU7(DGND) MODULE1.AU8(DGND) MODULE1.AU9(DGND) MODULE1.AU10(DGND) MODULE1.AU11(DGND) MODULE1.AU12(DGND) MODULE1.AU13(DGND) MODULE1.AU14(DGND) MODULE1.AU15(DGND) MODULE1.AU16(DGND) MODULE1.AU17(DGND) MODULE1.AU18(DGND) MODULE1.AU19(DGND) MODULE1.AU20(DGND) MODULE1.AU21(DGND) MODULE1.AU22(DGND) MODULE1.AU23(DGND) MODULE1.AU24(DGND) MODULE1.AU25(DGND) MODULE1.AU26(DGND) MODULE1.AU27(DGND) MODULE1.AU28(DGND) MODULE1.AU29(DGND) MODULE1.AU30(DGND) MODULE1.AU31(DGND) MODULE1.AU32(DGND) MODULE1.AU33(DGND) MODULE1.AU34(DGND) MODULE1.AU35(DGND) MODULE1.AU36(DGND) MODULE1.AU37(DGND) MODULE1.AU38(DGND) MODULE1.AU39(DGND) MODULE1.AU40(DGND) MODULE1.AU41(DGND) MODULE1.AU42(DGND) MODULE1.AU43(DGND) MODULE1.AU44(DGND) MODULE1.AV1(DGND) MODULE1.AV2(DGND) MODULE1.AV3(DGND) MODULE1.AV4(DGND) MODULE1.AV5(DGND) MODULE1.AV6(DGND) MODULE1.AV7(DGND) MODULE1.AV8(DGND) MODULE1.AV9(DGND) MODULE1.AV10(DGND) MODULE1.AV11(DGND) MODULE1.AV12(DGND) MODULE1.AV13(DGND) MODULE1.AV14(DGND) MODULE1.AV15(DGND) MODULE1.AV16(DGND) MODULE1.AV17(DGND) MODULE1.AV18(DGND) MODULE1.AV19(DGND) MODULE1.AV20(DGND) MODULE1.AV21(DGND) MODULE1.AV22(DGND) MODULE1.AV23(DGND) MODULE1.AV24(DGND) MODULE1.AV25(DGND) MODULE1.AV26(DGND) MODULE1.AV27(DGND) MODULE1.AV30(DGND) MODULE1.AV31(DGND) MODULE1.AV32(DGND) MODULE1.AV33(DGND) MODULE1.AV34(DGND) MODULE1.AV35(DGND) MODULE1.AV36(DGND) MODULE1.AV37(DGND) MODULE1.AV38(DGND) MODULE1.AV39(DGND) MODULE1.AV40(DGND) MODULE1.AV41(DGND) MODULE1.AV42(DGND) MODULE1.AV43(DGND) MODULE1.AV45(DGND) MODULE1.AW1(DGND) MODULE1.AW2(DGND) MODULE1.AW3(DGND) MODULE1.AW4(DGND) MODULE1.AW5(DGND) MODULE1.AW6(DGND) MODULE1.AW7(DGND) MODULE1.AW8(DGND) MODULE1.AW9(DGND) MODULE1.AW10(DGND) MODULE1.AW13(DGND) MODULE1.AW14(DGND) MODULE1.AW15(DGND) MODULE1.AW16(DGND) MODULE1.AW18(DGND) MODULE1.AW21(DGND) MODULE1.AW22(DGND) MODULE1.AW23(DGND) MODULE1.AW26(DGND) MODULE1.AW27(DGND) MODULE1.AW31(DGND) MODULE1.AW32(DGND) MODULE1.AW33(DGND) MODULE1.AW34(DGND) MODULE1.AW35(DGND) MODULE1.AW38(DGND) MODULE1.AW39(DGND) MODULE1.AW40(DGND) MODULE1.AW41(DGND) MODULE1.AW42(DGND) MODULE1.AW43(DGND) MODULE1.AW44(DGND) MODULE1.AY1(DGND) MODULE1.AY2(DGND) MODULE1.AY3(DGND) MODULE1.AY4(DGND) MODULE1.AY5(DGND) MODULE1.AY6(DGND) MODULE1.AY7(DGND) MODULE1.AY8(DGND) MODULE1.AY9(DGND) MODULE1.AY10(DGND) MODULE1.AY13(DGND) MODULE1.AY14(DGND) MODULE1.AY15(DGND) MODULE1.AY18(DGND) MODULE1.AY21(DGND) MODULE1.AY22(DGND) MODULE1.AY23(DGND) MODULE1.AY26(DGND) MODULE1.AY27(DGND) MODULE1.AY29(DGND) MODULE1.AY31(DGND) MODULE1.AY32(DGND) MODULE1.AY33(DGND) MODULE1.AY38(DGND) MODULE1.AY39(DGND) MODULE1.AY40(DGND) MODULE1.AY41(DGND) MODULE1.AY44(DGND) MODULE1.AY46(DGND) MODULE1.B1(DGND) MODULE1.B2(DGND) MODULE1.B3(DGND) MODULE1.B4(DGND) MODULE1.B6(DGND) MODULE1.B7(DGND) MODULE1.B8(DGND) MODULE1.B9(DGND) MODULE1.B10(DGND) MODULE1.B11(DGND) MODULE1.B12(DGND) MODULE1.B20(DGND) MODULE1.B22(DGND) MODULE1.B24(DGND) MODULE1.B26(DGND) MODULE1.B28(DGND) MODULE1.B30(DGND) MODULE1.B38(DGND) MODULE1.B39(DGND) MODULE1.B41(DGND) MODULE1.B42(DGND) MODULE1.B43(DGND) MODULE1.B44(DGND) MODULE1.B45(DGND) MODULE1.B46(DGND) MODULE1.BA2(DGND) MODULE1.BA3(DGND) MODULE1.BA4(DGND) MODULE1.BA5(DGND) MODULE1.BA6(DGND) MODULE1.BA7(DGND) MODULE1.BA8(DGND) MODULE1.BA9(DGND) MODULE1.BA10(DGND) MODULE1.BA12(DGND) MODULE1.BA13(DGND) MODULE1.BA14(DGND) MODULE1.BA15(DGND) MODULE1.BA16(DGND) MODULE1.BA17(DGND) MODULE1.BA18(DGND) MODULE1.BA19(DGND) MODULE1.BA20(DGND) MODULE1.BA21(DGND) MODULE1.BA22(DGND) MODULE1.BA23(DGND) MODULE1.BA24(DGND) MODULE1.BA25(DGND) MODULE1.BA26(DGND) MODULE1.BA27(DGND) MODULE1.BA28(DGND) MODULE1.BA30(DGND) MODULE1.BA32(DGND) MODULE1.BA39(DGND) MODULE1.BA40(DGND) MODULE1.BA41(DGND) MODULE1.BA44(DGND) MODULE1.BB2(DGND) MODULE1.BB3(DGND) MODULE1.BB4(DGND) MODULE1.BB5(DGND) MODULE1.BB6(DGND) MODULE1.BB7(DGND) MODULE1.BB8(DGND) MODULE1.BB9(DGND) MODULE1.BB10(DGND) MODULE1.BB11(DGND) MODULE1.BB12(DGND) MODULE1.BB13(DGND) MODULE1.BB14(DGND) MODULE1.BB15(DGND) MODULE1.BB16(DGND) MODULE1.BB17(DGND) MODULE1.BB18(DGND) MODULE1.BB19(DGND) MODULE1.BB20(DGND) MODULE1.BB21(DGND) MODULE1.BB22(DGND) MODULE1.BB23(DGND) MODULE1.BB24(DGND) MODULE1.BB25(DGND) MODULE1.BB26(DGND) MODULE1.BB27(DGND) MODULE1.BB30(DGND) MODULE1.BB32(DGND) MODULE1.BB34(DGND) MODULE1.BB35(DGND) MODULE1.BB36(DGND) MODULE1.BB40(DGND) MODULE1.BB41(DGND) MODULE1.BC1(DGND) MODULE1.BC2(DGND) MODULE1.BC3(DGND) MODULE1.BC4(DGND) MODULE1.BC5(DGND) MODULE1.BC6(DGND) MODULE1.BC7(DGND) MODULE1.BC8(DGND) MODULE1.BC11(DGND) MODULE1.BC12(DGND) MODULE1.BC15(DGND) MODULE1.BC16(DGND) MODULE1.BC19(DGND) MODULE1.BC20(DGND) MODULE1.BC23(DGND) MODULE1.BC24(DGND) MODULE1.BC27(DGND) MODULE1.BC30(DGND) MODULE1.BC32(DGND) MODULE1.BC34(DGND) MODULE1.BC35(DGND) MODULE1.BC41(DGND) MODULE1.BC42(DGND) MODULE1.BC43(DGND) MODULE1.BC44(DGND) MODULE1.BC45(DGND) MODULE1.BC46(DGND) MODULE1.BD1(DGND) MODULE1.BD2(DGND) MODULE1.BD3(DGND) MODULE1.BD4(DGND) MODULE1.BD5(DGND) MODULE1.BD8(DGND) MODULE1.BD9(DGND) MODULE1.BD12(DGND) MODULE1.BD13(DGND) MODULE1.BD16(DGND) MODULE1.BD17(DGND) MODULE1.BD18(DGND) MODULE1.BD19(DGND) MODULE1.BD20(DGND) MODULE1.BD21(DGND) MODULE1.BD22(DGND) MODULE1.BD23(DGND) MODULE1.BD24(DGND) MODULE1.BD25(DGND) MODULE1.BD26(DGND) MODULE1.BD27(DGND) MODULE1.BD30(DGND) MODULE1.BD32(DGND) MODULE1.BD34(DGND) MODULE1.BD43(DGND) MODULE1.BD44(DGND) MODULE1.BD45(DGND) MODULE1.BD46(DGND) MODULE1.BE1(DGND) MODULE1.BE2(DGND) MODULE1.BE3(DGND) MODULE1.BE4(DGND) MODULE1.BE5(DGND) MODULE1.BE6(DGND) MODULE1.BE7(DGND) MODULE1.BE8(DGND) MODULE1.BE9(DGND) MODULE1.BE10(DGND) MODULE1.BE13(DGND) MODULE1.BE14(DGND) MODULE1.BE17(DGND) MODULE1.BE18(DGND) MODULE1.BE21(DGND) MODULE1.BE24(DGND) MODULE1.BE25(DGND) MODULE1.BE27(DGND) MODULE1.BE30(DGND) MODULE1.BE32(DGND) MODULE1.BE34(DGND) MODULE1.BE43(DGND) MODULE1.BE44(DGND) MODULE1.BE45(DGND) MODULE1.BE46(DGND) MODULE1.BF2(DGND) MODULE1.BF3(DGND) MODULE1.BF4(DGND) MODULE1.BF7(DGND) MODULE1.BF10(DGND) MODULE1.BF11(DGND) MODULE1.BF14(DGND) MODULE1.BF15(DGND) MODULE1.BF18(DGND) MODULE1.BF19(DGND) MODULE1.BF22(DGND) MODULE1.BF25(DGND) MODULE1.BF27(DGND) MODULE1.BF30(DGND) MODULE1.BF32(DGND) MODULE1.BF34(DGND) MODULE1.BF43(DGND) MODULE1.BF44(DGND) MODULE1.BF45(DGND) MODULE1.C1(DGND) MODULE1.C2(DGND) MODULE1.C3(DGND) MODULE1.C4(DGND) MODULE1.C5(DGND) MODULE1.C6(DGND) MODULE1.C7(DGND) MODULE1.C8(DGND) MODULE1.C9(DGND) MODULE1.C10(DGND) MODULE1.C11(DGND) MODULE1.C12(DGND) MODULE1.C13(DGND) MODULE1.C14(DGND) MODULE1.C15(DGND) MODULE1.C16(DGND) MODULE1.C17(DGND) MODULE1.C18(DGND) MODULE1.C19(DGND) MODULE1.C20(DGND) MODULE1.C21(DGND) MODULE1.C22(DGND) MODULE1.C23(DGND) MODULE1.C24(DGND) MODULE1.C25(DGND) MODULE1.C26(DGND) MODULE1.C27(DGND) MODULE1.C36(DGND) MODULE1.C38(DGND) MODULE1.C40(DGND) MODULE1.C41(DGND) MODULE1.C42(DGND) MODULE1.C43(DGND) MODULE1.C44(DGND) MODULE1.C45(DGND) MODULE1.C46(DGND) MODULE1.D1(DGND) MODULE1.D2(DGND) MODULE1.D3(DGND) MODULE1.D4(DGND) MODULE1.D5(DGND) MODULE1.D6(DGND) MODULE1.D7(DGND) MODULE1.D8(DGND) MODULE1.D9(DGND) MODULE1.D10(DGND) MODULE1.D11(DGND) MODULE1.D12(DGND) MODULE1.D13(DGND) MODULE1.D14(DGND) MODULE1.D15(DGND) MODULE1.D16(DGND) MODULE1.D17(DGND) MODULE1.D18(DGND) MODULE1.D19(DGND) MODULE1.D20(DGND) MODULE1.D21(DGND) MODULE1.D22(DGND) MODULE1.D35(DGND) MODULE1.D38(DGND) MODULE1.D39(DGND) MODULE1.D40(DGND) MODULE1.D41(DGND) MODULE1.D42(DGND) MODULE1.D43(DGND) MODULE1.D44(DGND) MODULE1.D45(DGND) MODULE1.D46(DGND) MODULE1.E1(DGND) MODULE1.E2(DGND) MODULE1.E3(DGND) MODULE1.E4(DGND) MODULE1.E5(DGND) MODULE1.E6(DGND) MODULE1.E7(DGND) MODULE1.E8(DGND) MODULE1.E9(DGND) MODULE1.E10(DGND) MODULE1.E11(DGND) MODULE1.E12(DGND) MODULE1.E13(DGND) MODULE1.E14(DGND) MODULE1.E15(DGND) MODULE1.E16(DGND) MODULE1.E17(DGND) MODULE1.E18(DGND) MODULE1.E19(DGND) MODULE1.E20(DGND) MODULE1.E21(DGND) MODULE1.E22(DGND) MODULE1.E38(DGND) MODULE1.E39(DGND) MODULE1.E40(DGND) MODULE1.E41(DGND) MODULE1.E42(DGND) MODULE1.E43(DGND) MODULE1.E44(DGND) MODULE1.F1(DGND) MODULE1.F2(DGND) MODULE1.F3(DGND) MODULE1.F4(DGND) MODULE1.F5(DGND) MODULE1.F6(DGND) MODULE1.F7(DGND) MODULE1.F8(DGND) MODULE1.F9(DGND) MODULE1.F10(DGND) MODULE1.F11(DGND) MODULE1.F12(DGND) MODULE1.F13(DGND) MODULE1.F14(DGND) MODULE1.F15(DGND) MODULE1.F16(DGND) MODULE1.F17(DGND) MODULE1.F18(DGND) MODULE1.F19(DGND) MODULE1.F20(DGND) MODULE1.F21(DGND) MODULE1.F22(DGND) MODULE1.F23(DGND) MODULE1.F24(DGND) MODULE1.F25(DGND) MODULE1.F26(DGND) MODULE1.F29(DGND) MODULE1.F30(DGND) MODULE1.F31(DGND) MODULE1.F32(DGND) MODULE1.F33(DGND) MODULE1.F34(DGND) MODULE1.F35(DGND) MODULE1.F36(DGND) MODULE1.F37(DGND) MODULE1.F38(DGND) MODULE1.F39(DGND) MODULE1.F40(DGND) MODULE1.F41(DGND) MODULE1.F42(DGND) MODULE1.F43(DGND) MODULE1.F44(DGND) MODULE1.G1(DGND) MODULE1.G2(DGND) MODULE1.G3(DGND) MODULE1.G4(DGND) MODULE1.G5(DGND) MODULE1.G6(DGND) MODULE1.G7(DGND) MODULE1.G8(DGND) MODULE1.G9(DGND) MODULE1.G10(DGND) MODULE1.G11(DGND) MODULE1.G12(DGND) MODULE1.G13(DGND) MODULE1.G14(DGND) MODULE1.G15(DGND) MODULE1.G17(DGND) MODULE1.G18(DGND) MODULE1.G19(DGND) MODULE1.G20(DGND) MODULE1.G21(DGND) MODULE1.G22(DGND) MODULE1.G23(DGND) MODULE1.G24(DGND) MODULE1.G25(DGND) MODULE1.G26(DGND) MODULE1.G27(DGND) MODULE1.G28(DGND) MODULE1.G29(DGND) MODULE1.G30(DGND) MODULE1.G31(DGND) MODULE1.G32(DGND) MODULE1.G33(DGND) MODULE1.G34(DGND) MODULE1.G35(DGND) MODULE1.G36(DGND) MODULE1.G37(DGND) MODULE1.G38(DGND) MODULE1.G39(DGND) MODULE1.G40(DGND) MODULE1.G41(DGND) MODULE1.G42(DGND) MODULE1.G43(DGND) MODULE1.G44(DGND) MODULE1.H1(DGND) MODULE1.H2(DGND) MODULE1.H3(DGND) MODULE1.H4(DGND) MODULE1.H5(DGND) MODULE1.H6(DGND) MODULE1.H7(DGND) MODULE1.H8(DGND) MODULE1.H9(DGND) MODULE1.H10(DGND) MODULE1.H11(DGND) MODULE1.H12(DGND) MODULE1.H13(DGND) MODULE1.H14(DGND) MODULE1.H15(DGND) MODULE1.H17(DGND) MODULE1.H18(DGND) MODULE1.H19(DGND) MODULE1.H20(DGND) MODULE1.H21(DGND) MODULE1.H22(DGND) MODULE1.H23(DGND) MODULE1.H24(DGND) MODULE1.H25(DGND) MODULE1.H26(DGND) MODULE1.H27(DGND) MODULE1.H28(DGND) MODULE1.H29(DGND) MODULE1.H30(DGND) MODULE1.H31(DGND) MODULE1.H32(DGND) MODULE1.H33(DGND) MODULE1.H34(DGND) MODULE1.H35(DGND) MODULE1.H36(DGND) MODULE1.H37(DGND) MODULE1.H38(DGND) MODULE1.H39(DGND) MODULE1.H40(DGND) MODULE1.H41(DGND) MODULE1.H42(DGND) MODULE1.H43(DGND) MODULE1.H44(DGND) MODULE1.J1(DGND) MODULE1.J2(DGND) MODULE1.J3(DGND) MODULE1.J4(DGND) MODULE1.J5(DGND) MODULE1.J6(DGND) MODULE1.J7(DGND) MODULE1.J8(DGND) MODULE1.J9(DGND) MODULE1.J10(DGND) MODULE1.J11(DGND) MODULE1.J12(DGND) MODULE1.J13(DGND) MODULE1.J14(DGND) MODULE1.J15(DGND) MODULE1.J16(DGND) MODULE1.J17(DGND) MODULE1.J18(DGND) MODULE1.J19(DGND) MODULE1.J20(DGND) MODULE1.J21(DGND) MODULE1.J22(DGND) MODULE1.J23(DGND) MODULE1.J24(DGND) MODULE1.J25(DGND) MODULE1.J26(DGND) MODULE1.J27(DGND) MODULE1.J28(DGND) MODULE1.J29(DGND) MODULE1.J30(DGND) MODULE1.J31(DGND) MODULE1.J32(DGND) MODULE1.J33(DGND) MODULE1.J34(DGND) MODULE1.J35(DGND) MODULE1.J36(DGND) MODULE1.J37(DGND) MODULE1.J38(DGND) MODULE1.J39(DGND) MODULE1.J40(DGND) MODULE1.J41(DGND) MODULE1.J42(DGND) MODULE1.J43(DGND) MODULE1.J44(DGND) MODULE1.J45(DGND) MODULE1.J46(DGND) MODULE1.K1(DGND) MODULE1.K2(DGND) MODULE1.K3(DGND) MODULE1.K4(DGND) MODULE1.K5(DGND) MODULE1.K6(DGND) MODULE1.K7(DGND) MODULE1.K8(DGND) MODULE1.K9(DGND) MODULE1.K10(DGND) MODULE1.K11(DGND) MODULE1.K12(DGND) MODULE1.K13(DGND) MODULE1.K14(DGND) MODULE1.K15(DGND) MODULE1.K16(DGND) MODULE1.K17(DGND) MODULE1.K18(DGND) MODULE1.K19(DGND) MODULE1.K20(DGND) MODULE1.K21(DGND) MODULE1.K22(DGND) MODULE1.K23(DGND) MODULE1.K24(DGND) MODULE1.K25(DGND) MODULE1.K26(DGND) MODULE1.K27(DGND) MODULE1.K28(DGND) MODULE1.K29(DGND) MODULE1.K30(DGND) MODULE1.K31(DGND) MODULE1.K32(DGND) MODULE1.K33(DGND) MODULE1.K34(DGND) MODULE1.K35(DGND) MODULE1.K36(DGND) MODULE1.K37(DGND) MODULE1.K38(DGND) MODULE1.K39(DGND) MODULE1.K40(DGND) MODULE1.K41(DGND) MODULE1.K42(DGND) MODULE1.K43(DGND) MODULE1.K44(DGND) MODULE1.K45(DGND) MODULE1.L1(DGND) MODULE1.L2(DGND) MODULE1.L3(DGND) MODULE1.L4(DGND) MODULE1.L5(DGND) MODULE1.L6(DGND) MODULE1.L7(DGND) MODULE1.L8(DGND) MODULE1.L9(DGND) MODULE1.L10(DGND) MODULE1.L11(DGND) MODULE1.L12(DGND) MODULE1.L13(DGND) MODULE1.L14(DGND) MODULE1.L15(DGND) MODULE1.L16(DGND) MODULE1.L17(DGND) MODULE1.L18(DGND) MODULE1.L19(DGND) MODULE1.L20(DGND) MODULE1.L21(DGND) MODULE1.L22(DGND) MODULE1.L23(DGND) MODULE1.L24(DGND) MODULE1.L25(DGND) MODULE1.L26(DGND) MODULE1.L27(DGND) MODULE1.L28(DGND) MODULE1.L29(DGND) MODULE1.L30(DGND) MODULE1.L31(DGND) MODULE1.L32(DGND) MODULE1.L33(DGND) MODULE1.L34(DGND) MODULE1.L35(DGND) MODULE1.L36(DGND) MODULE1.L37(DGND) MODULE1.L38(DGND) MODULE1.L39(DGND) MODULE1.L40(DGND) MODULE1.L41(DGND) MODULE1.L42(DGND) MODULE1.L43(DGND) MODULE1.L44(DGND) MODULE1.M1(DGND) MODULE1.M2(DGND) MODULE1.M3(DGND) MODULE1.M4(DGND) MODULE1.M5(DGND) MODULE1.M6(DGND) MODULE1.M7(DGND) MODULE1.M8(DGND) MODULE1.M9(DGND) MODULE1.M10(DGND) MODULE1.M11(DGND) MODULE1.M12(DGND) MODULE1.M13(DGND) MODULE1.M14(DGND) MODULE1.M15(DGND) MODULE1.M16(DGND) MODULE1.M17(DGND) MODULE1.M18(DGND) MODULE1.M19(DGND) MODULE1.M20(DGND) MODULE1.M21(DGND) MODULE1.M22(DGND) MODULE1.M23(DGND) MODULE1.M24(DGND) MODULE1.M25(DGND) MODULE1.M26(DGND) MODULE1.M27(DGND) MODULE1.M28(DGND) MODULE1.M29(DGND) MODULE1.M30(DGND) MODULE1.M31(DGND) MODULE1.M32(DGND) MODULE1.M33(DGND) MODULE1.M34(DGND) MODULE1.M35(DGND) MODULE1.M36(DGND) MODULE1.M37(DGND) MODULE1.M38(DGND) MODULE1.M39(DGND) MODULE1.M40(DGND) MODULE1.M41(DGND) MODULE1.M42(DGND) MODULE1.M43(DGND) MODULE1.M44(DGND) MODULE1.N1(DGND) MODULE1.N2(DGND) MODULE1.N3(DGND) MODULE1.N4(DGND) MODULE1.N5(DGND) MODULE1.N6(DGND) MODULE1.N7(DGND) MODULE1.N8(DGND) MODULE1.N9(DGND) MODULE1.N10(DGND) MODULE1.N11(DGND) MODULE1.N12(DGND) MODULE1.N13(DGND) MODULE1.N14(DGND) MODULE1.N15(DGND) MODULE1.N16(DGND) MODULE1.N17(DGND) MODULE1.N18(DGND) MODULE1.N19(DGND) MODULE1.N20(DGND) MODULE1.N21(DGND) MODULE1.N22(DGND) MODULE1.N23(DGND) MODULE1.N24(DGND) MODULE1.N25(DGND) MODULE1.N26(DGND) MODULE1.N27(DGND) MODULE1.N28(DGND) MODULE1.N29(DGND) MODULE1.N30(DGND) MODULE1.N31(DGND) MODULE1.N32(DGND) MODULE1.N33(DGND) MODULE1.N34(DGND) MODULE1.N35(DGND) MODULE1.N36(DGND) MODULE1.N37(DGND) MODULE1.N38(DGND) MODULE1.N39(DGND) MODULE1.N40(DGND) MODULE1.N41(DGND) MODULE1.N42(DGND) MODULE1.N43(DGND) MODULE1.N44(DGND) MODULE1.N45(DGND) MODULE1.N46(DGND) MODULE1.P1(DGND) MODULE1.P2(DGND) MODULE1.P3(DGND) MODULE1.P4(DGND) MODULE1.P5(DGND) MODULE1.P6(DGND) MODULE1.P7(DGND) MODULE1.P8(DGND) MODULE1.P9(DGND) MODULE1.P10(DGND) MODULE1.P11(DGND) MODULE1.P12(DGND) MODULE1.P13(DGND) MODULE1.P14(DGND) MODULE1.P15(DGND) MODULE1.P16(DGND) MODULE1.P17(DGND) MODULE1.P18(DGND) MODULE1.P19(DGND) MODULE1.P20(DGND) MODULE1.P21(DGND) MODULE1.P22(DGND) MODULE1.P23(DGND) MODULE1.P24(DGND) MODULE1.P25(DGND) MODULE1.P26(DGND) MODULE1.P27(DGND) MODULE1.P28(DGND) MODULE1.P29(DGND) MODULE1.P30(DGND) MODULE1.P31(DGND) MODULE1.P32(DGND) MODULE1.P33(DGND) MODULE1.P34(DGND) MODULE1.P35(DGND) MODULE1.P36(DGND) MODULE1.P37(DGND) MODULE1.P38(DGND) MODULE1.P39(DGND) MODULE1.P40(DGND) MODULE1.P41(DGND) MODULE1.P42(DGND) MODULE1.P43(DGND) MODULE1.P44(DGND) MODULE1.R1(DGND) MODULE1.R2(DGND) MODULE1.R3(DGND) MODULE1.R4(DGND) MODULE1.R5(DGND) MODULE1.R6(DGND) MODULE1.R7(DGND) MODULE1.R8(DGND) MODULE1.R9(DGND) MODULE1.R10(DGND) MODULE1.R11(DGND) MODULE1.R12(DGND) MODULE1.R13(DGND) MODULE1.R14(DGND) MODULE1.R15(DGND) MODULE1.R16(DGND) MODULE1.R17(DGND) MODULE1.R18(DGND) MODULE1.R19(DGND) MODULE1.R20(DGND) MODULE1.R21(DGND) MODULE1.R22(DGND) MODULE1.R23(DGND) MODULE1.R24(DGND) MODULE1.R25(DGND) MODULE1.R29(DGND) MODULE1.R30(DGND) MODULE1.R31(DGND) MODULE1.R32(DGND) MODULE1.R33(DGND) MODULE1.R34(DGND) MODULE1.R35(DGND) MODULE1.R36(DGND) MODULE1.R37(DGND) MODULE1.R38(DGND) MODULE1.R39(DGND) MODULE1.R40(DGND) MODULE1.R41(DGND) MODULE1.R42(DGND) MODULE1.R43(DGND) MODULE1.R46(DGND) MODULE1.T1(DGND) MODULE1.T2(DGND) MODULE1.T3(DGND) MODULE1.T4(DGND) MODULE1.T5(DGND) MODULE1.T6(DGND) MODULE1.T7(DGND) MODULE1.T8(DGND) MODULE1.T9(DGND) MODULE1.T10(DGND) MODULE1.T11(DGND) MODULE1.T12(DGND) MODULE1.T13(DGND) MODULE1.T14(DGND) MODULE1.T15(DGND) MODULE1.T16(DGND) MODULE1.T17(DGND) MODULE1.T18(DGND) MODULE1.T19(DGND) MODULE1.T20(DGND) MODULE1.T21(DGND) MODULE1.T22(DGND) MODULE1.T32(DGND) MODULE1.T33(DGND) MODULE1.T34(DGND) MODULE1.T35(DGND) MODULE1.T36(DGND) MODULE1.T37(DGND) MODULE1.T38(DGND) MODULE1.T39(DGND) MODULE1.T40(DGND) MODULE1.T41(DGND) MODULE1.T42(DGND) MODULE1.T43(DGND) MODULE1.T44(DGND) MODULE1.U1(DGND) MODULE1.U2(DGND) MODULE1.U3(DGND) MODULE1.U4(DGND) MODULE1.U5(DGND) MODULE1.U6(DGND) MODULE1.U7(DGND) MODULE1.U8(DGND) MODULE1.U9(DGND) MODULE1.U10(DGND) MODULE1.U11(DGND) MODULE1.U12(DGND) MODULE1.U13(DGND) MODULE1.U14(DGND) MODULE1.U15(DGND) MODULE1.U16(DGND) MODULE1.U17(DGND) MODULE1.U18(DGND) MODULE1.U19(DGND) MODULE1.U20(DGND) MODULE1.U21(DGND) MODULE1.U22(DGND) MODULE1.U32(DGND) MODULE1.U33(DGND) MODULE1.U34(DGND) MODULE1.U35(DGND) MODULE1.U36(DGND) MODULE1.U37(DGND) MODULE1.U38(DGND) MODULE1.U39(DGND) MODULE1.U40(DGND) MODULE1.U42(DGND) MODULE1.U43(DGND) MODULE1.U46(DGND) MODULE1.V1(DGND) MODULE1.V2(DGND) MODULE1.V3(DGND) MODULE1.V4(DGND) MODULE1.V5(DGND) MODULE1.V6(DGND) MODULE1.V7(DGND) MODULE1.V8(DGND) MODULE1.V9(DGND) MODULE1.V10(DGND) MODULE1.V11(DGND) MODULE1.V12(DGND) MODULE1.V13(DGND) MODULE1.V14(DGND) MODULE1.V15(DGND) MODULE1.V16(DGND) MODULE1.V17(DGND) MODULE1.V18(DGND) MODULE1.V19(DGND) MODULE1.V20(DGND) MODULE1.V32(DGND) MODULE1.V33(DGND) MODULE1.V34(DGND) MODULE1.V35(DGND) MODULE1.V36(DGND) MODULE1.V37(DGND) MODULE1.V41(DGND) MODULE1.V44(DGND) MODULE1.W1(DGND) MODULE1.W2(DGND) MODULE1.W3(DGND) MODULE1.W4(DGND) MODULE1.W5(DGND) MODULE1.W6(DGND) MODULE1.W7(DGND) MODULE1.W8(DGND) MODULE1.W9(DGND) MODULE1.W10(DGND) MODULE1.W11(DGND) MODULE1.W12(DGND) MODULE1.W13(DGND) MODULE1.W14(DGND) MODULE1.W15(DGND) MODULE1.W16(DGND) MODULE1.W17(DGND) MODULE1.W18(DGND) MODULE1.W19(DGND) MODULE1.W32(DGND) MODULE1.W33(DGND) MODULE1.W34(DGND) MODULE1.W35(DGND) MODULE1.W36(DGND) MODULE1.W37(DGND) MODULE1.W44(DGND) MODULE1.W45(DGND) MODULE1.W46(DGND) MODULE1.Y1(DGND) MODULE1.Y2(DGND) MODULE1.Y3(DGND) MODULE1.Y4(DGND) MODULE1.Y5(DGND) MODULE1.Y6(DGND) MODULE1.Y7(DGND) MODULE1.Y8(DGND) MODULE1.Y9(DGND) MODULE1.Y10(DGND) MODULE1.Y11(DGND) MODULE1.Y12(DGND) MODULE1.Y13(DGND) MODULE1.Y14(DGND) MODULE1.Y15(DGND) MODULE1.Y16(DGND) MODULE1.Y17(DGND) MODULE1.Y32(DGND) MODULE1.Y33(DGND) MODULE1.Y34(DGND) MODULE1.Y35(DGND) MODULE1.Y36(DGND) MODULE1.Y37(DGND) MODULE1.Y44(DGND)

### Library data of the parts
MODULE1 = M0029-A.19: MODULE BGA 1883 balls 57.5x57.5mm; Manufacturer: Qualcomm; Code Arduino: M0029

## Sheet MODULE_PWR.SchDoc: MODULE PWR
size A3; Author: Silvio Navaretti; CompanyName: ARDUINO; DrawnBy: Silvio Navaretti; Engineer: Silvio Navaretti; Organization: ARDUINO; SheetNumber: 9; SheetTotal: 51; RevAuthor: Silvio Navaretti
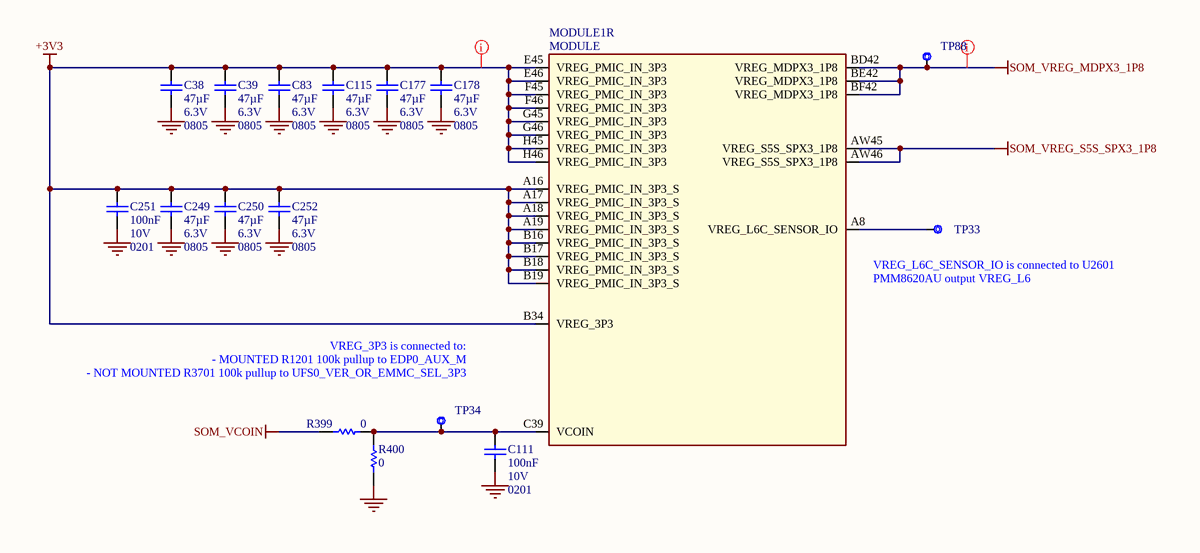
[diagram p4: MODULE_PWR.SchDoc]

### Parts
C38  value 47µF  Voltage: 6.3V  Case Code (Imperial): 0805  [CAP-0805]  (hidden comment: C0805C476M9PAC7800)
C39  value 47µF  Voltage: 6.3V  Case Code (Imperial): 0805  [CAP-0805]  (hidden comment: C0805C476M9PAC7800)
C83  value 47µF  Voltage: 6.3V  Case Code (Imperial): 0805  [CAP-0805]  (hidden comment: C0805C476M9PAC7800)
C111  value 100nF  Voltage: 10V  Case Code (Imperial): 0201  [CAP-0201]  (hidden comment: CL03A104KP3NNNC)
C115  value 47µF  Voltage: 6.3V  Case Code (Imperial): 0805  [CAP-0805]  (hidden comment: C0805C476M9PAC7800)
C177  value 47µF  Voltage: 6.3V  Case Code (Imperial): 0805  [CAP-0805]  (hidden comment: C0805C476M9PAC7800)
C178  value 47µF  Voltage: 6.3V  Case Code (Imperial): 0805  [CAP-0805]  (hidden comment: C0805C476M9PAC7800)
C249  value 47µF  Voltage: 6.3V  Case Code (Imperial): 0805  [CAP-0805]  (hidden comment: C0805C476M9PAC7800)
C250  value 47µF  Voltage: 6.3V  Case Code (Imperial): 0805  [CAP-0805]  (hidden comment: C0805C476M9PAC7800)
C251  value 100nF  Voltage: 10V  Case Code (Imperial): 0201  [CAP-0201]  (hidden comment: CL03A104KP3NNNC)
C252  value 47µF  Voltage: 6.3V  Case Code (Imperial): 0805  [CAP-0805]  (hidden comment: C0805C476M9PAC7800)
MODULE1  MODULE  [MODULE]  (part R of 22)
R399  value 0  [RES-0201]  (hidden comment: CRCW02010000Z0ED)
R400  value 0  [RES-0201]  (hidden comment: CRCW02010000Z0ED)
TP33  Test point 1.00mm  [TP-1.00MM]  (value not drawn)  (no BOM)
TP34  Test point 1.00mm  [TP-1.00MM]  (value not drawn)  (no BOM)
TP88  Test point 1.00mm  [TP-1.00MM]  (value not drawn)  (no BOM)

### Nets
+3V3: C38.2 C39.2 C83.2 C115.2 C177.2 C178.2 C249.2 C250.2 C251.2 C252.2 MODULE1.A16(VREG_PMIC_IN_3P3_S) MODULE1.A17(VREG_PMIC_IN_3P3_S) MODULE1.A18(VREG_PMIC_IN_3P3_S) MODULE1.A19(VREG_PMIC_IN_3P3_S) MODULE1.B16(VREG_PMIC_IN_3P3_S) MODULE1.B17(VREG_PMIC_IN_3P3_S) MODULE1.B18(VREG_PMIC_IN_3P3_S) MODULE1.B19(VREG_PMIC_IN_3P3_S) MODULE1.B34(VREG_3P3) MODULE1.E45(VREG_PMIC_IN_3P3) MODULE1.E46(VREG_PMIC_IN_3P3) MODULE1.F45(VREG_PMIC_IN_3P3) MODULE1.F46(VREG_PMIC_IN_3P3) MODULE1.G45(VREG_PMIC_IN_3P3) MODULE1.G46(VREG_PMIC_IN_3P3) MODULE1.H45(VREG_PMIC_IN_3P3) MODULE1.H46(VREG_PMIC_IN_3P3)
GND: C38.1 C39.1 C83.1 C111.1 C115.1 C177.1 C178.1 C249.1 C250.1 C251.1 C252.1 R400.1
SOM_VCOIN: R399.1
SOM_VREG_MDPX3_1P8: MODULE1.BD42(VREG_MDPX3_1P8) MODULE1.BE42(VREG_MDPX3_1P8) MODULE1.BF42(VREG_MDPX3_1P8) TP88.X
SOM_VREG_S5S_SPX3_1P8: MODULE1.AW45(VREG_S5S_SPX3_1P8) MODULE1.AW46(VREG_S5S_SPX3_1P8)
NetC111_2: C111.2 MODULE1.C39(VCOIN) R399.2 R400.2 TP34.X
NetMODULE1_A8: MODULE1.A8(VREG_L6C_SENSOR_IO) TP33.X

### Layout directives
net class NET_3V3: +3V3
net class NET_1V8_SOM: SOM_VREG_MDPX3_1P8

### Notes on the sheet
- VREG_L6C_SENSOR_IO is connected to U2601 PMM8620AU output VREG_L6
- VREG_3P3 is connected to:
  - MOUNTED R1201 100k pullup to EDP0_AUX_M
  - NOT MOUNTED R3701 100k pullup to UFS0_VER_OR_EMMC_SEL_3P3

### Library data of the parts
C38 C39 C83 C115 C177 C178 C249 C250 C252 = C0199-A.1: CAP CHIP 0805 47uF 20% 6.3V X5R; Manufacturer: KEMET; Code Arduino: C0199
C111 C251 = C0113-A.6: CAP CHIP 0201 100nF 10% 10V X5R; Manufacturer: Samsung Electro-Mechanics; Code Arduino: C0113
MODULE1 = M0029-A.19: as MODULE1 on sheet MODULE_GND
R399 R400 = R0140-A.21: RES CHIP 0201 0R; Manufacturer: Vishay; Temperature coefficient: 0ppm; Code Arduino: R0140; Power: 50mW; Tolerance: 0%
TP33 TP34 TP88 = UT0013-A.6: Part Number: This is not a component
